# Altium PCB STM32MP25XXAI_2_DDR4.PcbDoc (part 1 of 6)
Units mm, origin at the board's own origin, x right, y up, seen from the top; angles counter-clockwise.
Board outline 172 x 137 mm, 4 copper layers (Top Layer, Signal Layer 1, Signal Layer 2, Bottom Layer), stack 1.614 mm thick; 241 components, 153 nets, 1312 pads, 924 vias.
Unrouted connection lines stored in the file: 13.
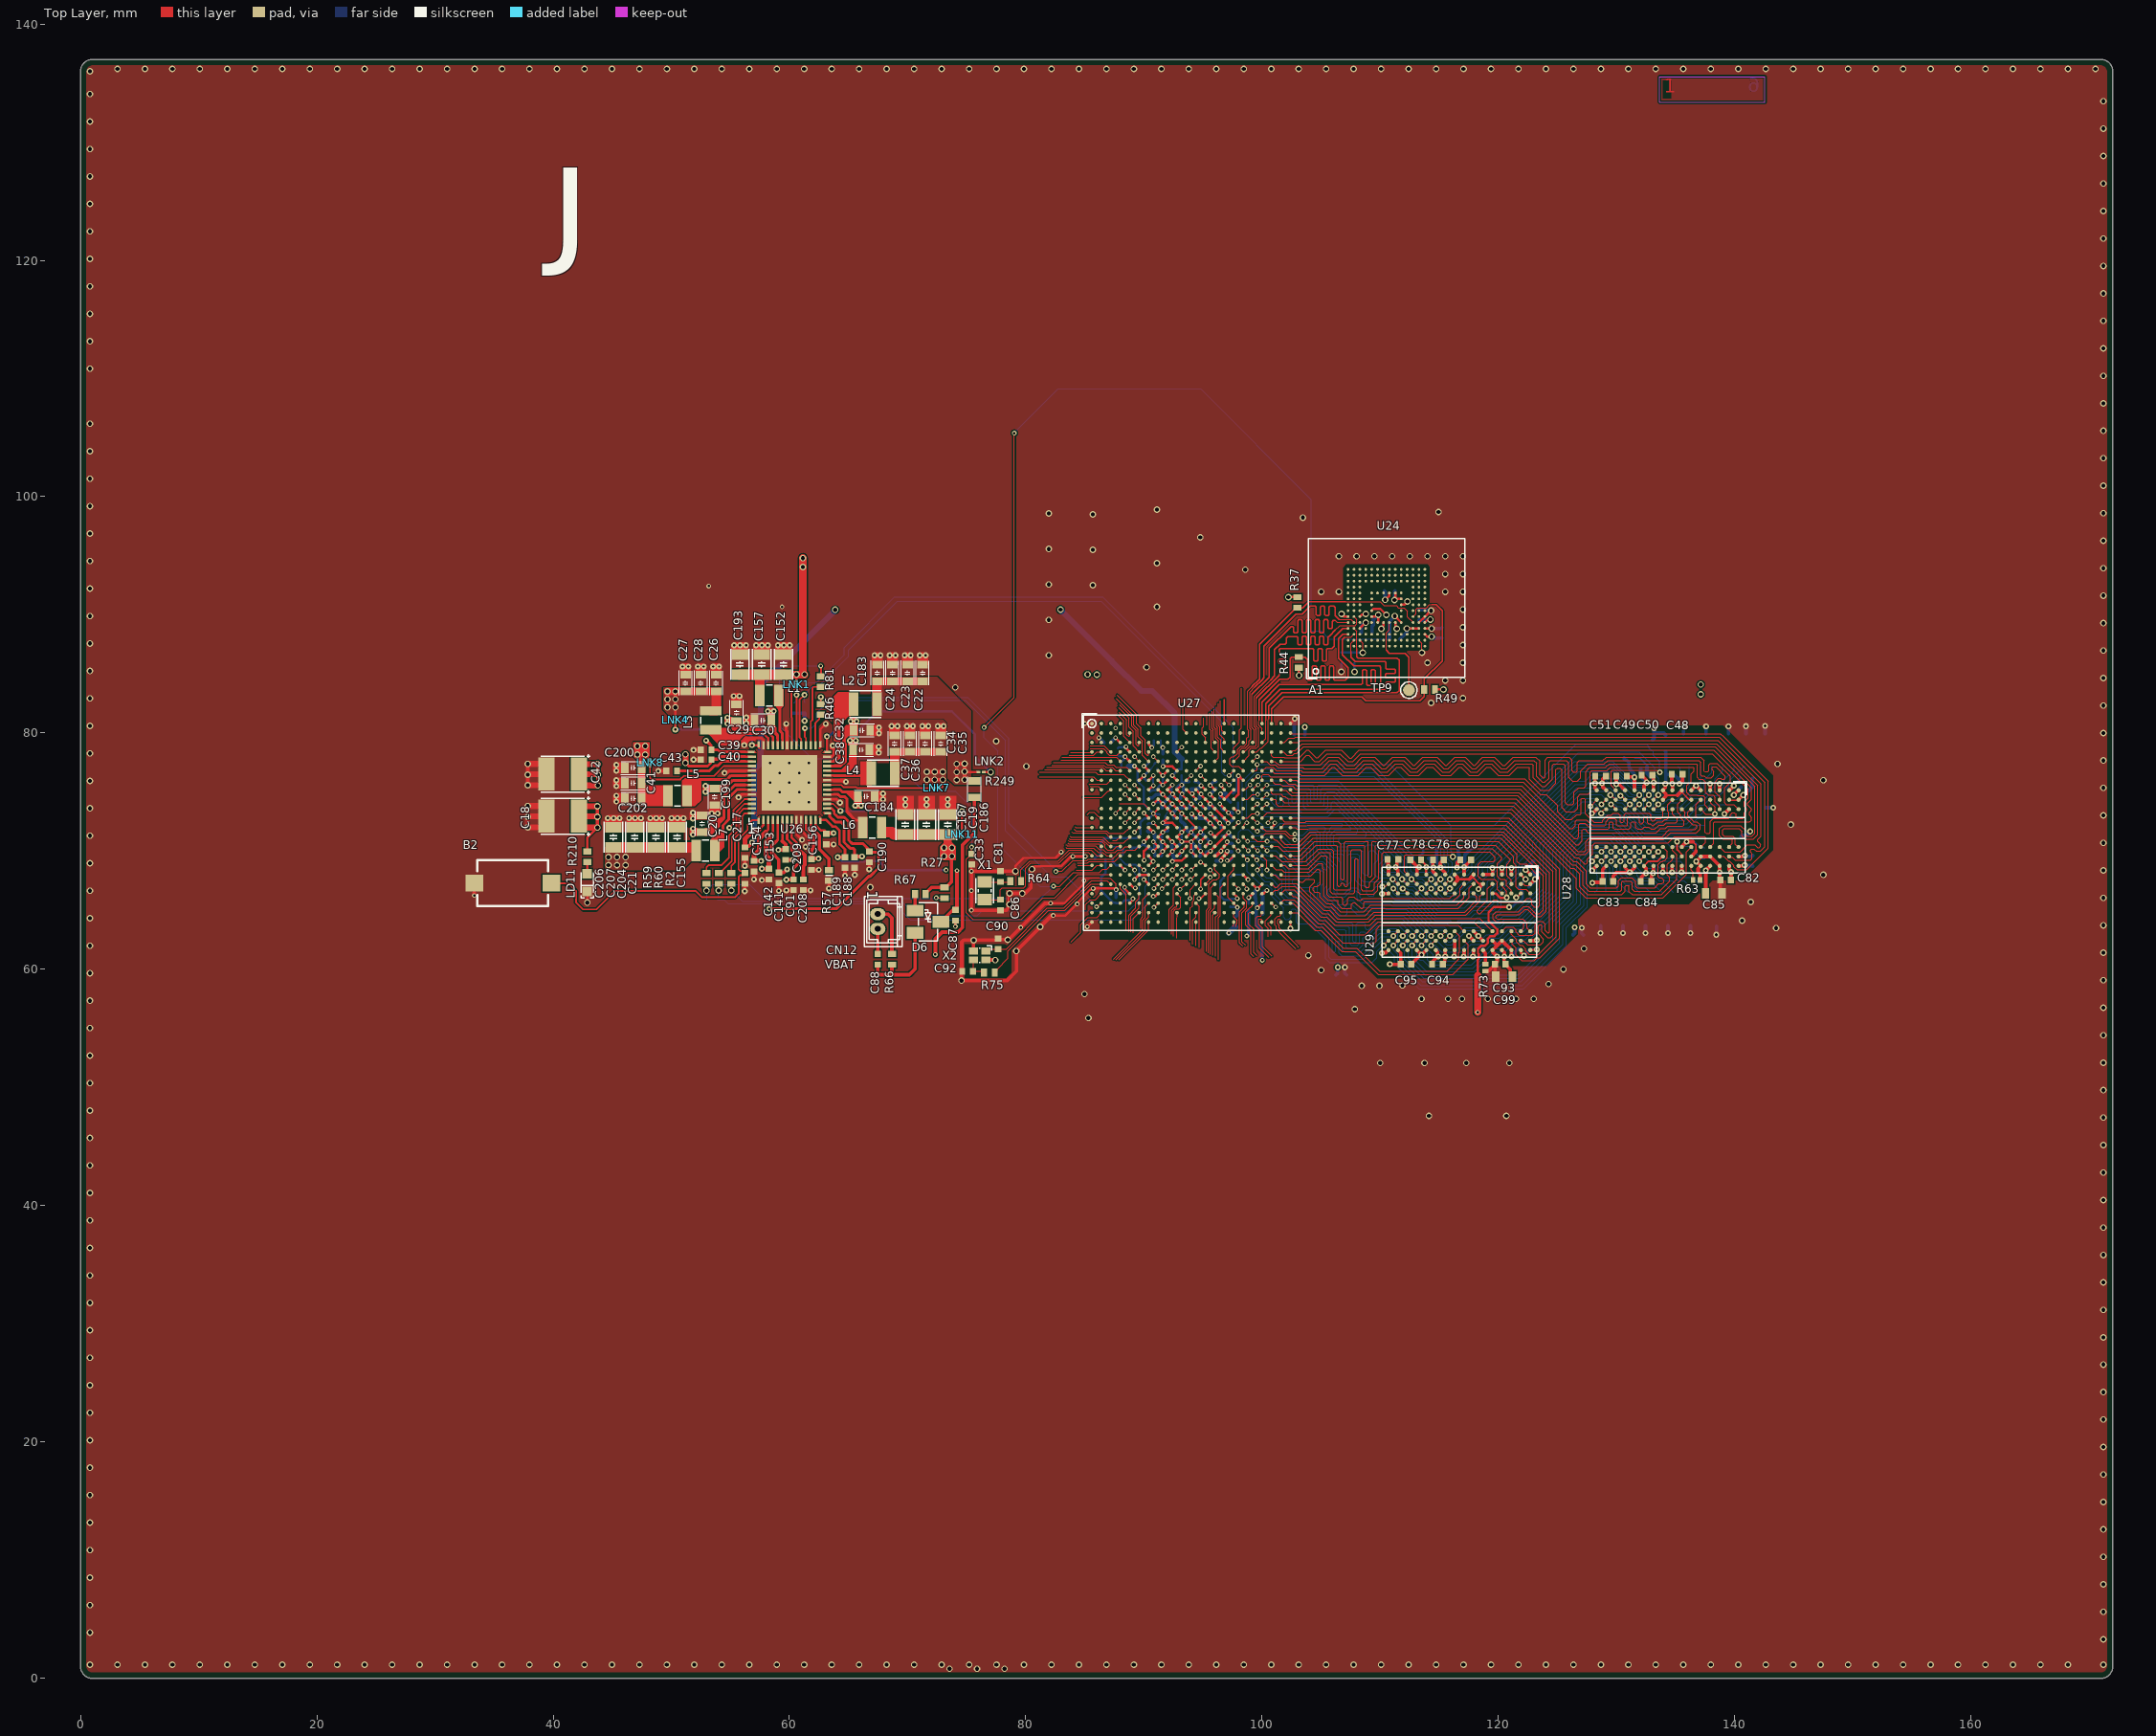
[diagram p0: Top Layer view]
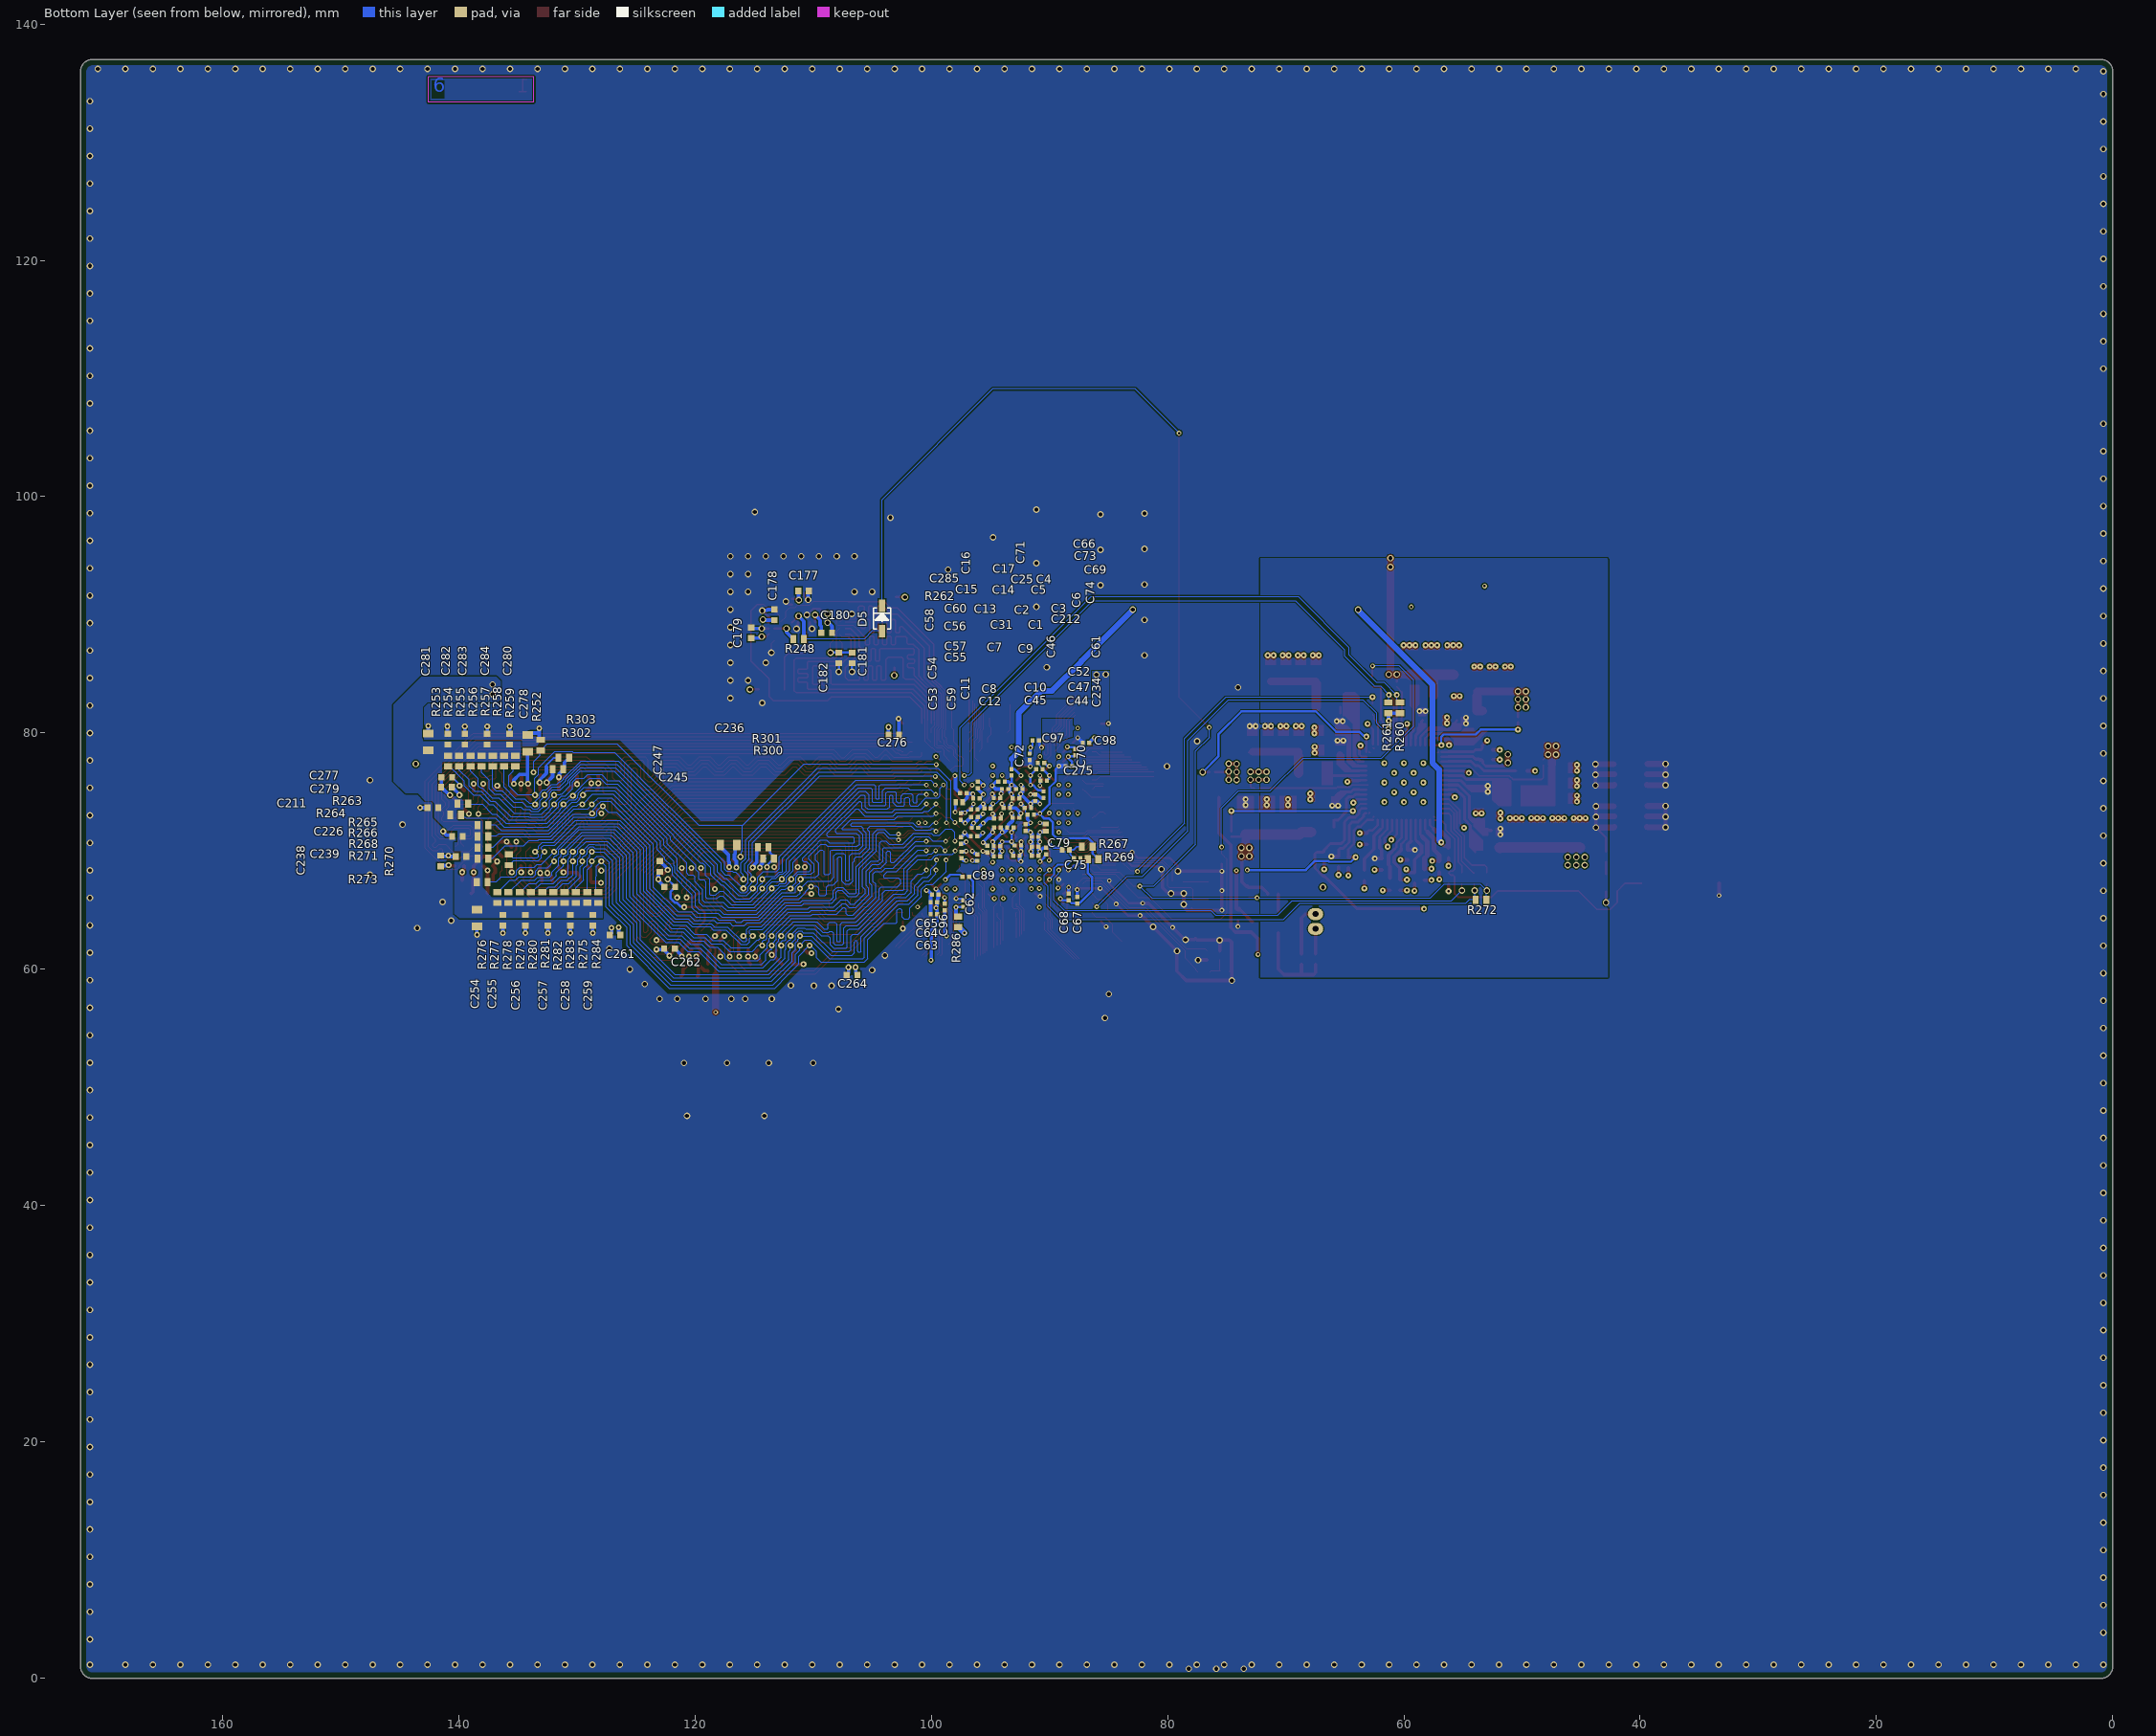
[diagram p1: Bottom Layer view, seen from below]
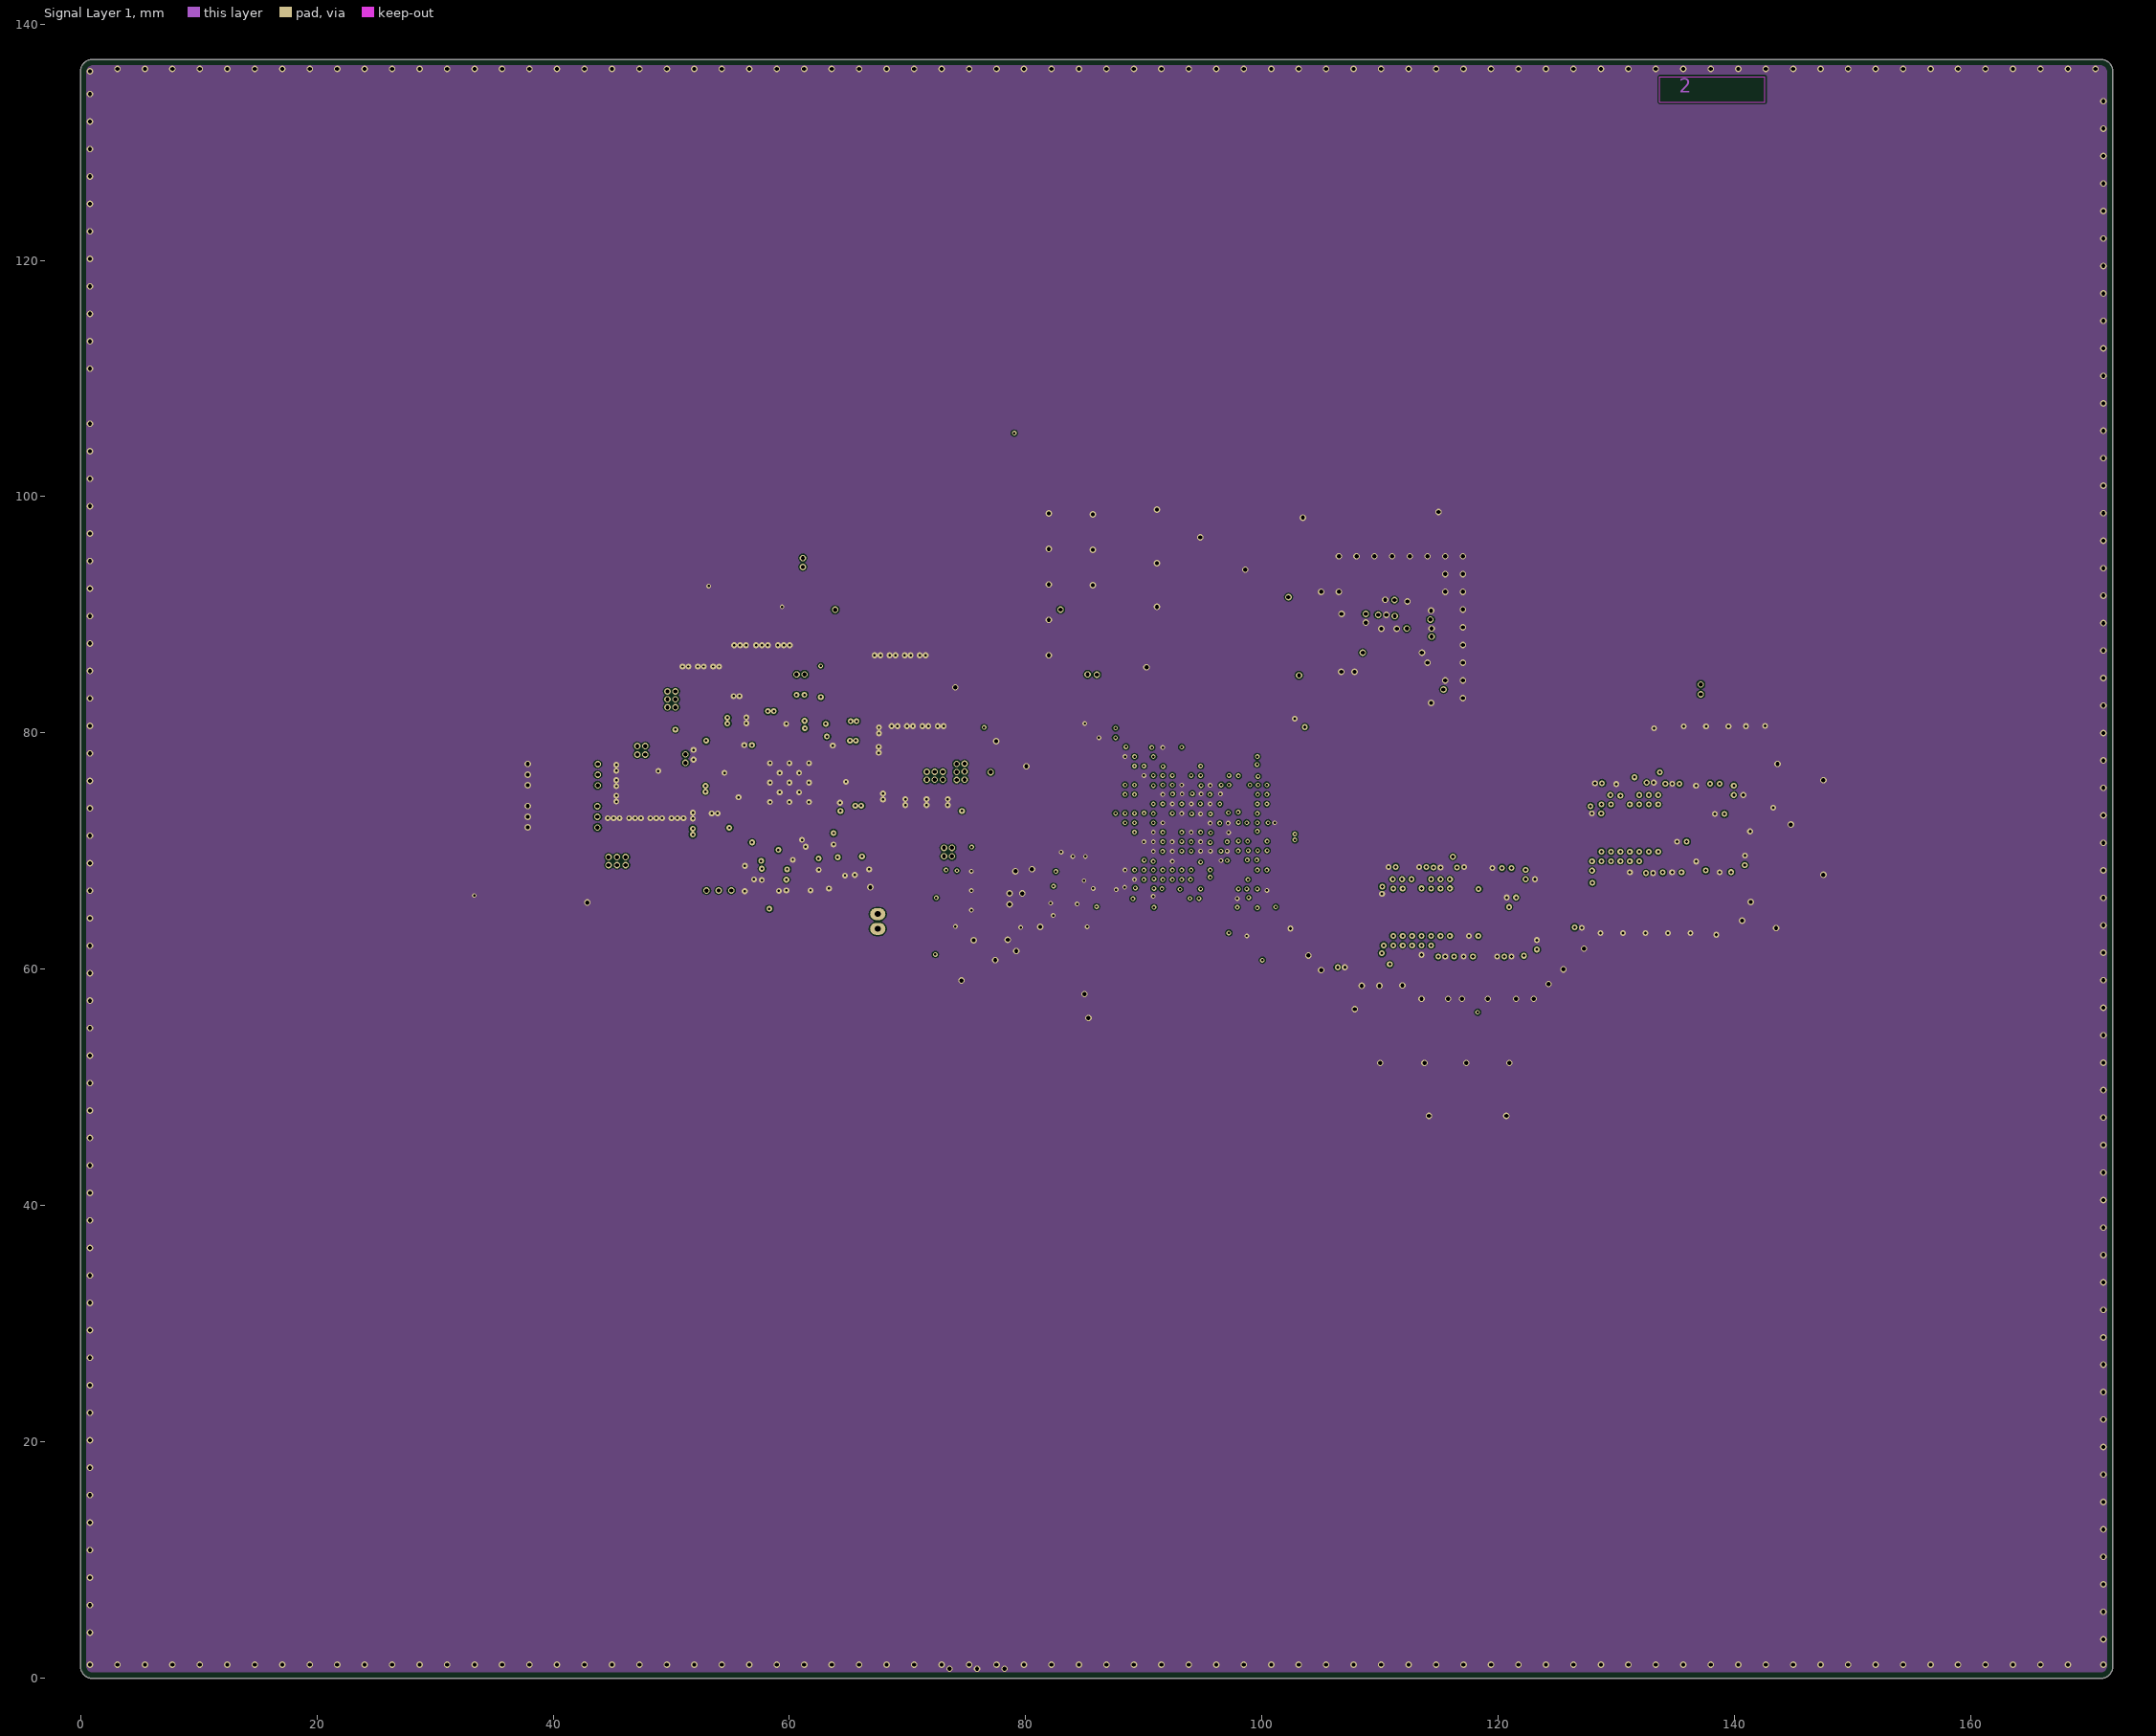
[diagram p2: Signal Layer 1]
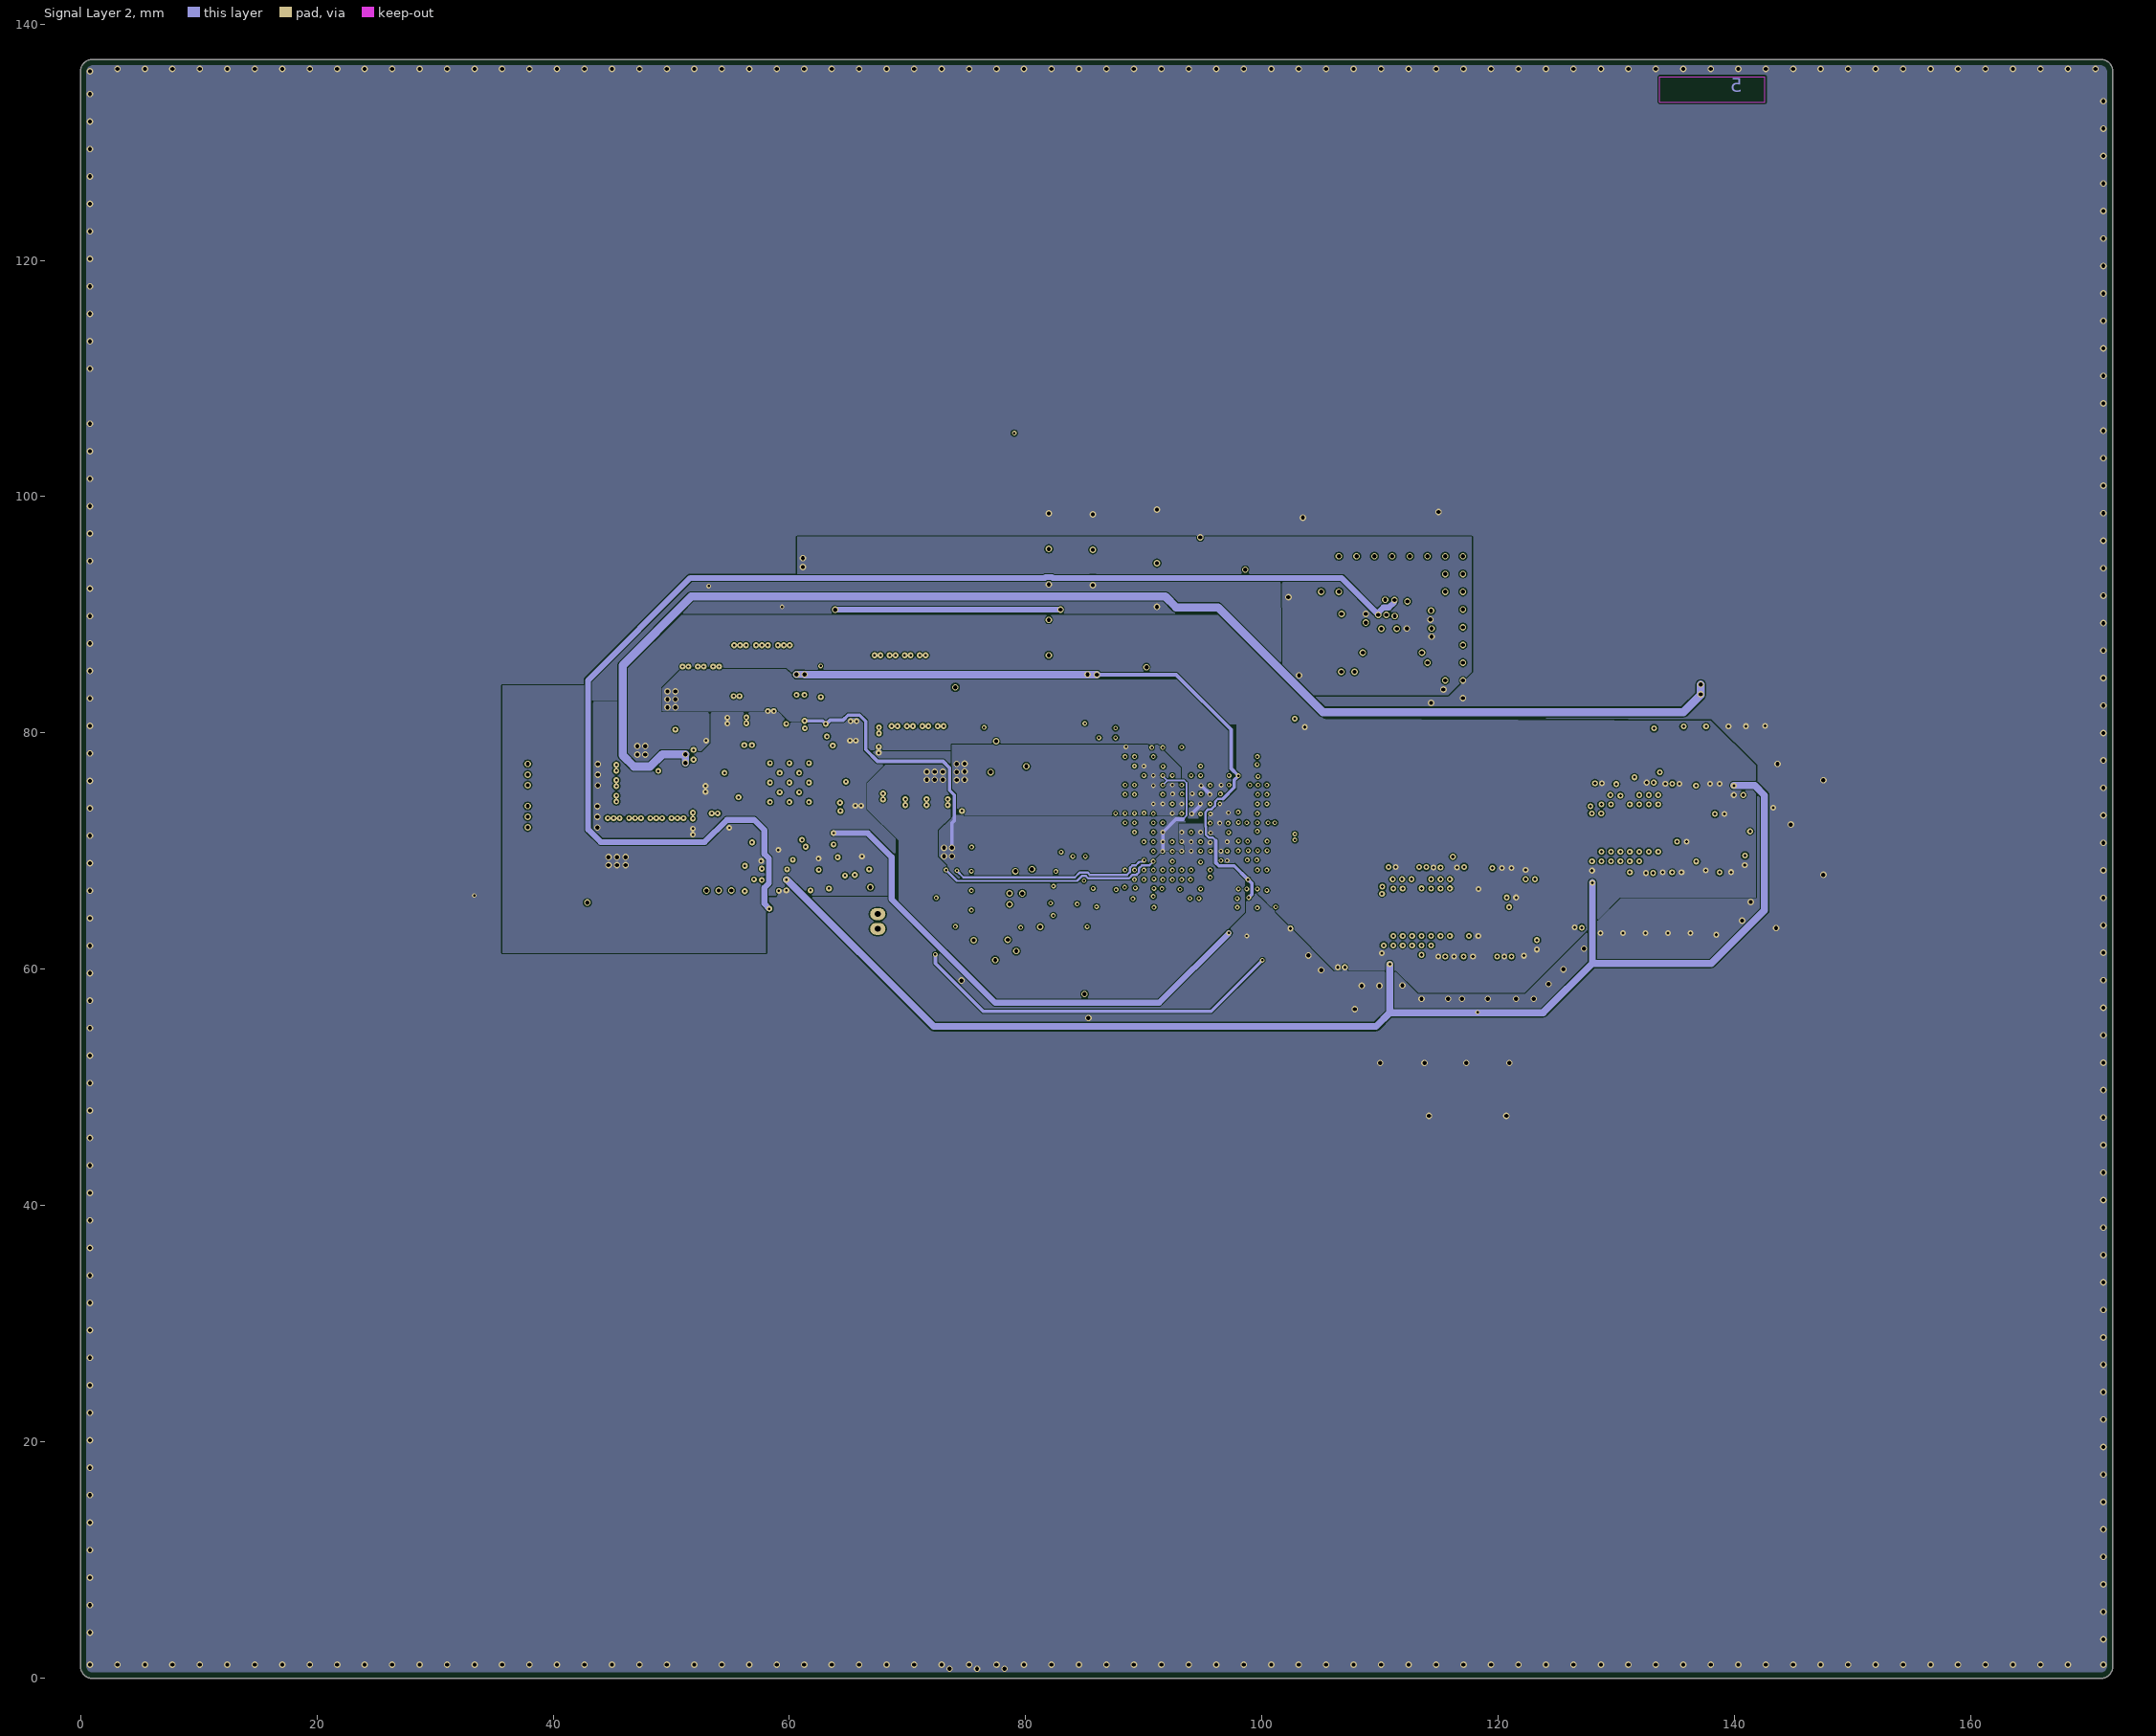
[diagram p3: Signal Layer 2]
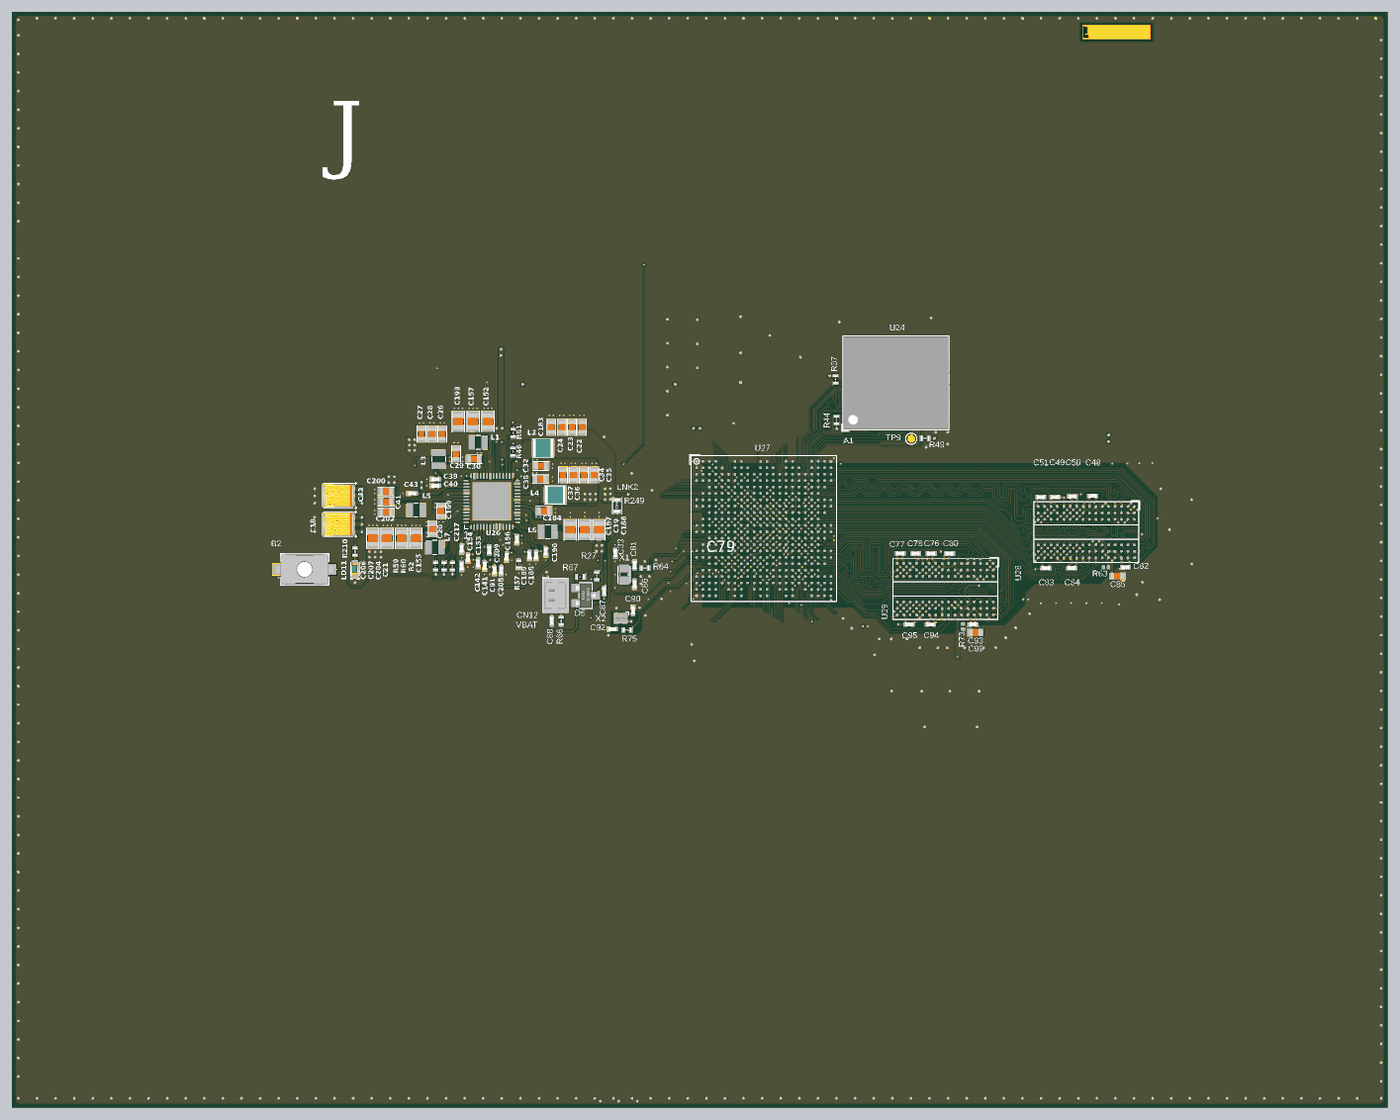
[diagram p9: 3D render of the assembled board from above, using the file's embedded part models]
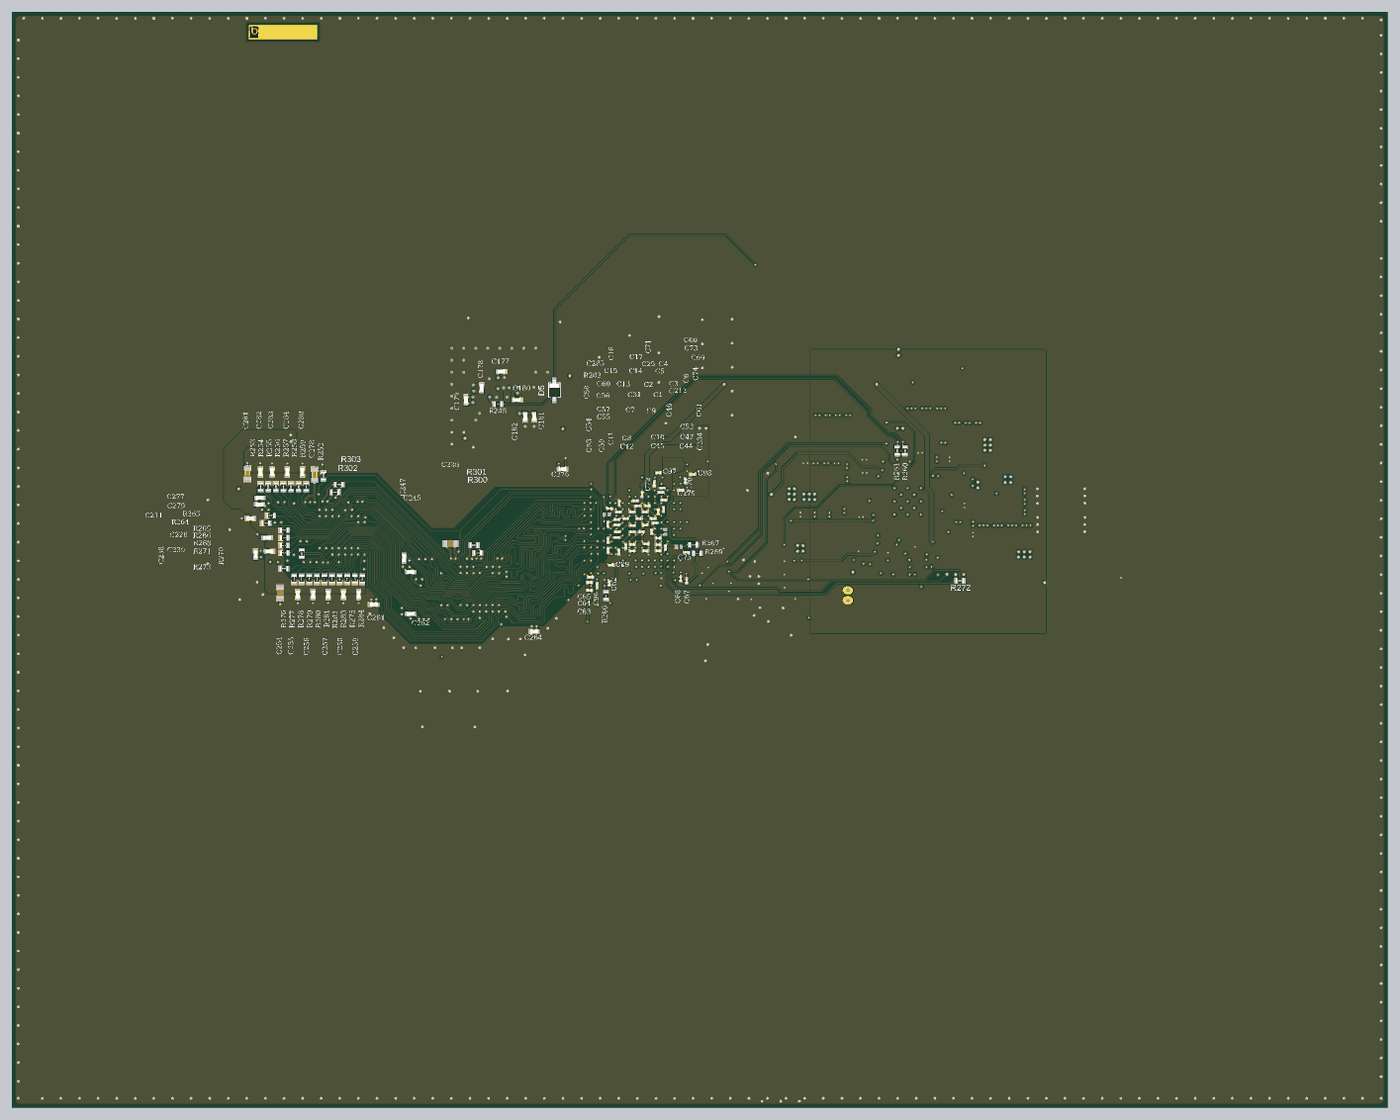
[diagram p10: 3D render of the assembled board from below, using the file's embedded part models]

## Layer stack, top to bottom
Top Solder: solder mask 0.025, Solder Resist, Dk 3.5
Top Layer: signal copper 0.037
Dielectric 1: prepreg 0.07, Dk 3.8
Signal Layer 1: signal copper 0.035
Dielectric 2: core 1.33, Dk 4.3
Signal Layer 2: signal copper 0.035
Dielectric 3: prepreg 0.07, Dk 3.8
Bottom Layer: signal copper 0.037
Bottom Solder: solder mask 0.025, Solder Resist, Dk 3.5

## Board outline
0,1 0,95 0,136 cw(c1,136) 1,137 171,137 cw(c171,136) 172,136 172,1 cw(c171,1) 171,0 1,0 cw(c1,1)

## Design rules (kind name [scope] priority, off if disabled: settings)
BoardOutlineClearance Silkscreen [OnLayer('Top Overlay') or OnLayer('Bottom Overlay')] p1: gap=0 ignorepadtopadclearanceinfootprint=FALSE
BoardOutlineClearance [All] p2: gap=0.5 ignorepadtopadclearanceinfootprint=FALSE
Clearance Clearance_Default [All] p1: gap=0.1 ignorepadtopadclearanceinfootprint=TRUE except(0: Arc-Hole Track-Hole SMDPad-Hole THPad-Hole Via-Hole Fill-Hole Poly-Hole Region-Hole Text-Hole; 0.09: Track-Track Track-SMDPad)
ComponentClearance [All] p1 off: gap=0.2 collisioncheckmode=3 verticalgap=0 showdistances=FALSE
DiffPairsRouting DiffPairsRouting_DDR_100R [InDifferentialPairClass('DPC_DDR_100R')] p1: maxlimit=0.16 minlimit=0.14 mostfreqgap=0.254 toplayer_mingap=0.16 toplayer_prefgap=0.16 toplayer_minwidth=0.09 toplayer_maxwidth=0.09 toplayer_prefwidth=0.09 bottomlayer_mingap=0.16 bottomlayer_prefgap=0.16 bottomlayer_minwidth=0.09 bottomlayer_maxwidth=0.09 bottomlayer_prefwidth=0.09 impedanceprofiledriven=TRUE impedanceprofileid={5106416E-43F8-41F8-8BCA-F68B3FB1C141} impedanceprofilevalue=100.000000 maxuncoupledlength=12.7
FanoutControl Fanout_BGA [IsBGA] p1: bgadir=Out bgaviamode=Closest fanoutstyle=Auto fanoutdirection=Alternating viagrid=0.025 // Fanout_BGA (Default Rule)
FanoutControl Fanout_LCC [IsLCC] p2: bgadir=Out bgaviamode=Closest fanoutstyle=Auto fanoutdirection=Alternating viagrid=0.025 // Fanout_LCC (Default Rule)
FanoutControl Fanout_SOIC [IsSOIC] p3: bgadir=Out bgaviamode=Closest fanoutstyle=Auto fanoutdirection=Alternating viagrid=0.025 // Fanout_SOIC (Default Rule)
FanoutControl Fanout_Small [(CompPinCount < 5)] p4: bgadir=Out bgaviamode=Closest fanoutstyle=Auto fanoutdirection=OutThenIn viagrid=0.025 // Fanout_Small (Default Rule)
FanoutControl Fanout_Default [All] p5: bgadir=Out bgaviamode=Closest fanoutstyle=Auto fanoutdirection=Alternating viagrid=0.025 // Fanout_Default (Default Rule)
HoleSize [All] p1: absolutevalues=TRUE maxlimit=10 minlimit=0.025 maxpercent=80.000 minpercent=20.000
HoleToHoleClearance [All] p1: gap=0.25 allowstackedmicrovias=TRUE
MinimumSolderMaskSliver [All] p1: minsoldermaskwidth=0.07
PlaneConnect [All] p1: planeconnectstyle=Direct reliefexpansion=0.508 reliefentries=4 reliefconductorwidth=0.21 reliefairgap=0.21
PolygonConnect PolygonConnect_Default [All] p1: connectstyle=Direct reliefconductorwidth=0.25 reliefentries=4 polygonreliefangle="90 Angle" airgapwidth=0.25
RoutingVias RoutingVias_Default [All] p1: holewidth=0.15 width=0.4 viastyle="Through Hole" minholewidth=0.15 minwidth=0.4 maxholewidth=0.35 maxwidth=0.6 viatemplateguid#1={BF886351-5902-4D8E-87A9-DD407FAE4AFA} viatemplateguid#2={A479BBDC-94B7-4D18-B59D-B7A18B767B5F} viatemplateguid#3={564DD7E2-F718-4BCE-8A99-5417C9FECCB6} viatemplateguid#4={BB8F4C89-420F-4EBC-9772-FD82009DE81A} viatemplateguid#5={3FF096CA-B7A5-4E0B-A50A-8B2CD18CCC19} viatemplatename#1=v50h25m30mx30 viatemplatename#2=v55h35m40mx40 viatemplatename#3=v40h20m0mx0 viatemplatename#4=v40h20m25mx25 viatemplatename#5=v50h25m0mx0
ShortCircuit ShortCircuit_Link200 [InPadClass('PC_LINK200')] p1: allowed=TRUE
SilkToSilkClearance [All] p1: silktosilkclearance=0.2
SilkToSolderMaskClearance [IsPad] p1: minsilkscreentomaskgap=0.015 clearancetoexposedcopper=TRUE
SolderMaskExpansion [All] p1: expansion=0.1 istentingtop=FALSE
ViasUnderSMD [InPadClass('PC_VIAS-IN-PAD_OK')] p1: allowed=TRUE
Width Width_Default [InNetClass('All Nets')] p1: maxlimit=10 minlimit=0.09 preferedwidth=0.1
16 further rules are at their usual default settings.

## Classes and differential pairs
differential pair DDR_DQS3: +DDR_DQS3_P -DDR_DQS3_N
differential pair DDR_DQS2: +DDR_DQS2_P -DDR_DQS2_N
differential pair DDR_DQS1: +DDR_DQS1_P -DDR_DQS1_N
differential pair DDR_DQS0: +DDR_DQS0_P -DDR_DQS0_N
differential pair DDR_CLK: +DDR_CLK_P -DDR_CLK_N

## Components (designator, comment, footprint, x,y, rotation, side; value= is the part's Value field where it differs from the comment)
B2 "SW_PUSH_SMD_2P" SWI_WE_434121025816 36.59,67.295 r0 top value=434121025816
C1 "Capacitor" C0201_MURATA_GRM033_H0P3 92.825,72.825 r0 bottom value=1uF
C2 "Capacitor" C0201_MURATA_GRM033_H0P3 93.601,73.65 r180 bottom value=1uF
C3 "Capacitor" C0201_MURATA_GRM033_H0P3 91.825,73.65 r180 bottom value=1uF
C4 "Capacitor" C0201_MURATA_GRM033_H0P3 92.55,75.25 r0 bottom value=1uF
C5 "Capacitor" C0201_MURATA_GRM033_H0P3 92.826,74.475 r180 bottom value=1uF
C6 "Capacitor" C0201_MURATA_GRM033_H0P3 91.2,74.525 r270 bottom value=1uF
C7 "Capacitor" C0201_MURATA_GRM033_H0P3 94.4,72 r0 bottom value=1uF
C8 "Capacitor" C0201_MURATA_GRM033_H0P3 94.425,70.425 r180 bottom value=1uF
C9 "Capacitor" C0201_MURATA_GRM033_H0P3 93.3,72 r180 bottom value=1uF
C10 "Capacitor" C0201_MURATA_GRM033_H0P3 92.675,70.48 r0 bottom value=1uF
C11 "Capacitor" C0201_MURATA_GRM033_H0P3 95.25,70.175 r270 bottom value=1uF
C12 "Capacitor" C0201_MURATA_GRM033_H0P3 94.425,69.575 r180 bottom value=1uF
C13 "Capacitor" C0201_MURATA_GRM033_H0P3 95.232,73.625 r0 bottom value=1uF
C14 "Capacitor" C0201_MURATA_GRM033_H0P3 94.425,74.48 r180 bottom value=1uF
C15 "Capacitor" C0201_MURATA_GRM033_H0P3 96.175,74.475 r180 bottom value=1uF
C16 "Capacitor" C0201_MURATA_GRM033_H0P3 96.075,75.6 r90 bottom value=1uF
C17 "Capacitor" C0201_MURATA_GRM033_H0P3 94.05,75.875 r0 bottom value=1uF
C18 "Cap_POL_TANA" CPOL_TCJ-B_1210_H210 40.812,72.961 r180 top value=100uF
C19 "Capacitor" C0805 71.6,72.25 r270 top value=22uF
C20 "Capacitor" C0603 52.6,72.325 r270 top value=10uF
C21 "Capacitor" C0805 50.5,71.173 r270 top value=22uF
C22 "Capacitor" C0603 71.275,85.075 r270 top value=22uF
C23 "Capacitor" C0603 70,85.075 r270 top value=22uF
C24 "Capacitor" C0603 68.725,85.075 r270 top value=22uF
C25 "Capacitor" C0201_MURATA_GRM033_H0P3 93.75,75.25 r0 bottom value=1uF
C26 "Capacitor" C0603 53.8,84.225 r270 top value=22uF
C27 "Capacitor" C0603 51.2,84.225 r270 top value=22uF
C28 "Capacitor" C0603 52.5,84.225 r270 top value=22uF
C29 "Capacitor" C0603 55.525,81.725 r270 top value=10uF
C30 "Capacitor" C0603 57.75,81.075 r0 top value=10uF
C31 "Capacitor" C0201_MURATA_GRM033_H0P3 94.4,72.775 r180 bottom value=1uF
C32 "Capacitor" C0603 66.125,80.225 r180 top value=10uF
C33 "Capacitor" C0402 75.425,69.325 r90 top value=10nF
C34 "Capacitor" C0603 71.5,79.1 r270 top value=22uF
C35 "Capacitor" C0603 72.8,79.1 r270 top value=22uF
C36 "Capacitor" C0603 70.2,79.1 r270 top value=22uF
C37 "Capacitor" C0603 68.9,79.1 r270 top value=22uF
C38 "Capacitor" C0603 66.075,78.575 r180 top value=10uF
C39 "Capacitor" C0402 52.945,78.575 r0 top value=10uF
C40 "Capacitor" C0402 52.945,77.75 r0 top value=10uF
C41 "Capacitor" C0603 46.775,75.75 r0 top value=22uF
C42 "Cap_POL_TANA" CPOL_TCJ-B_1210_H210 40.812,76.523 r180 top value=100uF
C43 "Capacitor" C0402 50.035,76.8 r0 top value=1uF
C44 "Capacitor" C0201_MURATA_GRM033_H0P3 91.2,69.6 r180 bottom value=1uF
C45 "Capacitor" C0201_MURATA_GRM033_H0P3 92.8,69.6 r0 bottom value=1uF
C46 "Capacitor" C0201_MURATA_GRM033_H0P3 92.025,72 r270 bottom value=1uF
C47 "Capacitor" C0201_MURATA_GRM033_H0P3 91.2,70.388 r180 bottom value=1uF
C48 "Capacitor" C0402 135.125,76.5 r0 top value=100nF
C49 "Capacitor" C0402 130.425,76.35 r0 top value=100nF
C50 "Capacitor" C0402 132.575,76.425 r180 top value=100nF
C51 "Capacitor" C0402 128.65,76.35 r0 top value=100nF
C52 "Capacitor" C0201_MURATA_GRM033_H0P3 91.2,71.2 r0 bottom value=1uF
C53 "Capacitor" C0201_MURATA_GRM033_H0P3 97.45,69.675 r270 bottom value=1uF
C54 "Capacitor" C0201_MURATA_GRM033_H0P3 97.475,70.9 r90 bottom value=1uF
C55 "Capacitor" C0201_MURATA_GRM033_H0P3 96.375,71.275 r180 bottom value=1uF
C56 "Capacitor" C0201_MURATA_GRM033_H0P3 96.349,72.875 r180 bottom value=1uF
C57 "Capacitor" C0201_MURATA_GRM033_H0P3 96.301,71.974 r0 bottom value=1uF
C58 "Capacitor" C0201_MURATA_GRM033_H0P3 97.5,72.925 r90 bottom value=1uF
C59 "Capacitor" C0201_MURATA_GRM033_H0P3 96.1,69.45 r90 bottom value=1uF
C60 "Capacitor" C0201_MURATA_GRM033_H0P3 96.356,73.524 r0 bottom value=1uF
C61 "Capacitor" C0201_H0P5 90.317,71.988 r90 bottom value=4.7uF
C62 "Capacitor" C0201_MURATA_GRM033_H0P3 97.3,65.575 r270 bottom value=100nF
C63 "Capacitor" C0201_MURATA_GRM033_H0P3 99.775,64.675 r180 bottom value=100nF
C64 "Capacitor" C0201_MURATA_GRM033_H0P3 99.775,65.675 r180 bottom value=100nF
C65 "Capacitor" C0201_MURATA_GRM033_H0P3 99.65,66.325 r180 bottom value=100nF
C66 "Capacitor" C0201_MURATA_GRM033_H0P3 90.7,77.475 r180 bottom value=100nF
C67 "Capacitor" C0201_MURATA_GRM033_H0P3 87.63,65.845 r270 bottom value=1uF
C68 "Capacitor" C0201_MURATA_GRM033_H0P3 88.375,66.125 r270 bottom value=100nF
C69 "Capacitor" C0201_MURATA_GRM033_H0P3 90.48,75.97 r0 bottom value=100nF
C70 "Capacitor" C0201_MURATA_GRM033_H0P3 87.8,78.375 r90 bottom value=100nF
C71 "Capacitor" C0201_MURATA_GRM033_H0P3 93.201,76.675 r90 bottom value=100nF
C72 "Capacitor" C0201_MURATA_GRM033_H0P3 91.675,77.975 r270 bottom value=100nF
C73 "Capacitor" C0201_MURATA_GRM033_H0P3 90.85,76.925 r0 bottom value=100nF
C74 "Capacitor" C0201_MURATA_GRM033_H0P3 90.5,74.775 r90 bottom value=100nF
C75 "Capacitor" C0201_MURATA_GRM033_H0P3 87.65,69.425 r0 bottom value=100nF
C76 "Capacitor" C0402 114.925,69.275 r180 top value=100nF
C77 "Capacitor" C0402 111.075,69.3 r0 top value=100nF
C78 "Capacitor" C0402 113,69.275 r0 top value=100nF
C79 "Capacitor" C0201_H0P5 88.6,70.125 r180 bottom value=2.2uF
C80 "Capacitor" C0402 117.225,69.275 r180 top value=100nF
C81 "Capacitor" C0402 77.85,67.85 r90 top value=6.8pF
C82 "Capacitor" C0402 139.225,67.55 r0 top value=100nF
C83 "Capacitor" C0402 129.275,67.45 r180 top value=100nF
C84 "Capacitor" C0402 132.5,67.45 r180 top value=100nF
C85 "Capacitor" C0603 138.225,66.425 r180 top value=10uF
C86 "Capacitor" C0402 77.85,65.45 r270 top value=6.8pF
C87 "" C0402 74.05,64.575 r90 top value=100nF
C88 "Capacitor" C0402 67.475,60.85 r270 top value=2.2uF
C89 "Capacitor" C0201_MURATA_GRM033_H0P3 97.075,67.825 r0 bottom value=100nF
C90 "Capacitor" C0402 77.65,62.15 r270 top value=6.8pF
C91 "Capacitor" C0402 60.345,67.16 r270 top value=4.7uF
C92 "Capacitor" C0402 75.075,59.825 r180 top value=6.8pF
C93 "Capacitor" C0402 120.15,60.425 r0 top value=100nF
C94 "Capacitor" C0402 114.844,60.422 r180 top value=100nF
C95 "Capacitor" C0402 112.175,60.425 r180 top value=100nF
C96 "Capacitor" C0201_MURATA_GRM033_H0P3 98.85,65.275 r90 bottom value=100nF
C97 "Capacitor" C0201_MURATA_GRM033_H0P3 91.15,79.375 r180 bottom value=100nF
C98 "Capacitor" C0201_MURATA_GRM033_H0P3 86.9,79.175 r0 bottom value=100nF
C99 "Capacitor" C0603 120.475,59.4 r0 top value=10uF
C141 "Capacitor" C0402 59.1,67.75 r270 top value=4.7uF
C142 "Capacitor" C0402 58.275,68.06 r270 top value=4.7uF
C152 "Capacitor" C0805 59.5,85.8 r270 top value=22uF
C153 "Capacitor" C0402 59.675,69.72 r90 top value=1uF
C154 "Capacitor" C0402 57,68.725 r90 top value=1uF
C155 "Capacitor" C0402 56.227,67.695 r90 top value=10nF
C156 "Capacitor" C0402 63.125,71.02 r90 top value=4.7uF
C157 "Capacitor" C0805 57.65,85.8 r270 top value=22uF
C177 "Capacitor" C0402 110.8,92.025 r0 bottom value=100nF
C178 "Capacitor" C0402 113.275,90 r270 bottom value=2.2uF
C179 "Capacitor" C0402 115.225,88.475 r270 bottom value=100nF
C180 "Capacitor" C0402 108.85,88.475 r0 bottom value=2.2uF
C181 "Capacitor" C0402 106.7,86.35 r90 bottom value=2.2uF
C182 "Capacitor" C0402 107.825,86.35 r90 bottom value=100nF
C183 "Capacitor" C0603 67.45,85.075 r270 top value=22uF
C184 "Capacitor" C0603 66.497,74.625 r180 top value=10uF
C186 "Capacitor" C0805 73.4,72.25 r270 top value=22uF
C187 "Capacitor" C0805 69.8,72.25 r270 top value=22uF
C188 "Capacitor" C0402 65.525,69.04 r90 top value=1uF
C189 "Capacitor" C0402 64.7,69.04 r90 top value=4.7uF
C190 "Capacitor" C0402 66.75,69.515 r270 top value=4.7uF
C193 "Capacitor" C0805 55.8,85.8 r270 top value=22uF
C199 "Capacitor" C0603 53.675,74.6 r90 top value=10uF
C200 "Capacitor" C0603 46.775,77.05 r0 top value=22uF
C202 "Capacitor" C0603 46.775,74.45 r0 top value=22uF
C204 "Capacitor" C0805 48.7,71.173 r270 top value=22uF
C206 "Capacitor" C0805 45.1,71.173 r270 top value=22uF
C207 "Capacitor" C0805 46.9,71.173 r270 top value=22uF
C208 "Capacitor" C0402 61.17,67.16 r270 top value=4.7uF
C209 "Capacitor" C0402 61.85,68.87 r90 top value=4.7uF
C211 "Capacitor" C0402 142.175,73.675 r180 bottom value=100nF
C212 "Capacitor" C0201_MURATA_GRM033_H0P3 91.585,73.1 r180 bottom value=100nF
C217 "Capacitor" C0402 56.225,69.87 r270 top value=4.7uF
C226 "Capacitor" C0402 140.1,71.25 r180 bottom value=100nF
C234 "Capacitor" C0201_MURATA_GRM033_H0P3 90.275,70.01 r270 bottom value=100nF
C236 "Capacitor" C0603 117.15,70.525 r180 bottom value=10uF
C238 "Capacitor" C0402 141.525,69.175 r270 bottom value=100nF
C239 "Capacitor" C0402 139.8,69.55 r180 bottom value=100nF
C245 "Capacitor" C0402 122.125,66.975 r180 bottom value=100nF
C247 "Capacitor" C0402 122.975,68.7 r90 bottom value=100nF
C254 "Capacitor" C0603 138.45,64.35 r90 bottom value=10uF
C255 "Capacitor" C0402 136.25,64.15 r90 bottom value=100nF
C256 "Capacitor" C0402 134.35,64.15 r90 bottom value=100nF
C257 "Capacitor" C0402 132.45,64.15 r90 bottom value=100nF
C258 "Capacitor" C0402 130.55,64.15 r90 bottom value=100nF
C259 "Capacitor" C0402 128.65,64.15 r90 bottom value=100nF
C261 "Capacitor" C0402 126.75,62.9 r180 bottom value=100nF
C262 "Capacitor" C0402 122.15,61.75 r0 bottom value=100nF
C264 "Capacitor" C0402 106.7,59.525 r180 bottom value=100nF
C275 "Capacitor" C0201_MURATA_GRM033_H0P3 88.35,77.2 r0 bottom value=100nF
C276 "Capacitor" C0402 103.17,79.846 r0 bottom value=100nF
C277 "Capacitor" C0402 141,76.25 r180 bottom value=100nF
C278 "Capacitor" C0603 134.15,79.125 r270 bottom value=10uF
C279 "Capacitor" C0402 141.025,75.425 r180 bottom value=100nF
C280 "Capacitor" C0402 135.675,79.475 r270 bottom value=100nF
C281 "Capacitor" C0603 142.575,79.25 r270 bottom value=10uF
C282 "Capacitor" C0402 140.925,79.475 r270 bottom value=100nF
C283 "Capacitor" C0402 139.475,79.475 r270 bottom value=100nF
C284 "Capacitor" C0402 137.575,79.475 r270 bottom value=100nF
C285 "Capacitor" C0201_MURATA_GRM033_H0P3 97.28,74.91 r0 bottom value=100nF
CN12 "" CON_MOLEX_53047-0210 67.475,64.05 r270 top value="Header 2x1"
D5 "BAT60JFILM" DIO_SOD323 104.175,89.7 r90 bottom
D6 "DIODE_3P_DUAL_COMMON_CATHODE" DIO_SOT23 71.725,64.025 r270 top value=BAT54CFILM
L1 "Inductor" IND_2016_MURATA_LQM2MPN2R2NG0 58.295,83.175 r180 top value=2.2uH
L2 "Inductor" IND_2520_TOKO_DFE252012P 66.415,82.45 r0 top value=0.68µH
L3 "Inductor" IND_2016_MURATA_LQM2MPN2R2NG0 53.35,81.075 r90 top value=0.68uH
L4 "Inductor" IND_2520_TOKO_DFE252012P 67.925,76.6 r0 top value=0.68µH
L5 "Inductor" IND_2016_MURATA_LQM2MPN2R2NG0 50.525,74.7 r180 top value=0.68uH
L6 "Inductor" IND_2016_MURATA_LQM2MPN2R2NG0 67,72 r0 top value=2.2uH
L7 "Inductor" IND_2016_MURATA_LQM2MPN2R2NG0 52.9,70.05 r180 top value=0.68uH
LD11 "LED_green" LED_0603_OSRAM_LG-Q396-PS-35_GREEN_1A2K_H0P4 42.887,67.327 r270 top value=GREEN
LNK1 "link_200" LINK200 60.6,84.123 r0 top
LNK2 "link_200" LINK200 76.219,76.687 r90 top
LNK4 "link_200" LINK200 50.35,81.125 r180 top
LNK7 "link_200" LINK200 72.45,75.35 r270 top
LNK8 "link_200" LINK200 48.2,77.498 r0 top
LNK11 "link_200" LINK200 74.6,71.44 r180 top
R2 "" R0402 55.08,67.695 r90 top value=0R
R27 "Resistor" R0402 73.125,66.475 r90 top value=10K
R37 "Resistor" R0402 102.975,91.05 r90 top value=10K
R44 "Resistor" R0402 103.1,85.978 r270 top value=10K
R46 "" R0402 62.65,81.998 r270 top value=0R
R49 "Resistor" R0402 114.175,83.685 r0 top value=10K
R57 "" R0402 63.35,67.95 r90 top value=0R
R59 "" R0402 52.98,67.695 r90 top value=0R
R60 "" R0402 54.03,67.695 r90 top value=0R
R63 "Resistor" R0201_H0P23 136.775,67.55 r180 top value=240R
R64 "" R0402 79.15,67.45 r180 top value=0R
R66 "Resistor" R0402 68.675,60.845 r270 top value=20R
R67 "Resistor" R0402 71.075,66.375 r0 top value=0R
R73 "Resistor" R0201_H0P23 118.9,60.15 r90 top value=240R
R75 "" R0402 76.925,59.725 r0 top value=0R
R81 "" R0402 62.663,84.348 r270 top value=0R
R210 "Resistor" R0402 42.887,69.52 r270 top value=270R
R248 "Resistor" R0402 111.225,87.95 r0 bottom value=10K
R249 "Resistor" R0603 75.65,75.25 r270 top value=0R
R252 "Resistor" R0402 133.05,78.975 r270 bottom value=10K
R253 "Resistor" R0402 140.9,77.625 r90 bottom value=56R
R254 "Resistor" R0402 139.95,77.625 r90 bottom value=56R
R255 "Resistor" R0402 139,77.625 r90 bottom value=56R
R256 "Resistor" R0402 138.05,77.625 r90 bottom value=56R
R257 "Resistor" R0402 137.1,77.625 r90 bottom value=56R
R258 "Resistor" R0402 136.15,77.625 r90 bottom value=56R
R259 "Resistor" R0402 135.2,77.625 r90 bottom value=56R
R260 "Resistor" R0402 60.33,82.13 r270 bottom value=1K5
R261 "Resistor" R0402 61.305,82.13 r270 bottom value=1K5
R262 "Resistor" R0201_H0P23 97.624,74.149 r0 bottom value=240R
R263 "Resistor" R0402 139.65,74.025 r0 bottom value=56R
R264 "Resistor" R0402 140.25,73.075 r0 bottom value=56R
R265 "Resistor" R0402 137.95,72.2 r0 bottom value=56R
R266 "Resistor" R0402 137.95,71.25 r0 bottom value=56R
R267 "" R0402 86.8,70.375 r180 bottom value=0R
R268 "Resistor" R0402 137.95,70.3 r0 bottom value=56R
R269 "" R0402 86.304,69.315 r0 bottom value=0R
R270 "Resistor" R0402 135.75,69.275 r90 bottom value=100R
R271 "Resistor" R0402 137.95,69.35 r0 bottom value=56R
R272 "Resistor" R0402 53.475,65.879 r0 bottom value=10K
R273 "Resistor" R0402 138,67.375 r0 bottom value=56R
R275 "Resistor" R0402 129.12,66.08 r270 bottom value=56R
R276 "Resistor" R0402 136.725,66.075 r270 bottom value=56R
R277 "Resistor" R0402 135.775,66.075 r270 bottom value=56R
R278 "Resistor" R0402 134.825,66.075 r270 bottom value=56R
R279 "Resistor" R0402 133.875,66.075 r270 bottom value=56R
R280 "Resistor" R0402 132.925,66.075 r270 bottom value=56R
R281 "Resistor" R0402 131.975,66.075 r270 bottom value=56R
R282 "Resistor" R0402 131.025,66.075 r270 bottom value=56R
R283 "Resistor" R0402 130.075,66.075 r270 bottom value=56R
R284 "Resistor" R0402 128.175,66.075 r270 bottom value=56R
R286 "" R0402 97.725,64.025 r90 bottom value=0R
R300 "Resistor" R0402 113.775,69.375 r0 bottom value=1K
R301 "Resistor" R0402 114.225,70.325 r180 bottom value=1K
R302 "Resistor" R0402 131.6,76.95 r0 bottom value=1K
R303 "Resistor" R0402 131.1,77.9 r180 bottom value=1K
TP9 "Test Point" TP_SMD_1MM 112.43,83.629 r90 top value=N/A
U24 "eMMC_THGBMTG5D1LBAIL" ICC_P-WFBGA153_13X11P5_P050 110.525,90.6 r0 top locked value=THGBMTG5D1LBAIL
U26 "STPMIC25APQR" ICC_QFN56-EPAD_6P5X6P5_P040 60,75.8 r90 top
U27 "STM32MP257FAI3" ICC_LFBGA436_18X18_P080_H1P70_STM32MP257_CODE-B0D1 94,72.4 r0 top locked
U28 "MT40A1G16TB-062E IT:F" ICC_FBGA96_TB_7P5X13_P080 134.325,71.95 r270 top locked
U29 "MT40A1G16TB-062E IT:F" ICC_FBGA96_TB_7P5X13_P080 116.7,64.825 r270 top locked
X1 "XTAL_2_PINS" CRY_NX2012SA_2P 76.525,66.65 r270 top value=32.768KHz
X2 "XTAL_4_PINS" CRY_NX1612SA_4P 76.098,61.176 r180 top value=40MHz

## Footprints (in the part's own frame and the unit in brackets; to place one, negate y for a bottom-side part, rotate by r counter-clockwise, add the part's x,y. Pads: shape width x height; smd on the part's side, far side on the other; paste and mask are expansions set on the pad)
C0201_H0P5 [mm] "MCD-01534"
  rect 0.4x0.5 smd mask+0.05: 1(-0.3,0) 2(0.3,0)
  body extent -0.35,-0.2 0.35,0.2, height 0.55
C0201_MURATA_GRM033_H0P3 [mm] "GRM033R60J105ME11"
  rect 0.35x0.35 smd mask+0.05: 1(-0.275,0) 2(0.275,0)
  body extent -0.32,-0.17 0.32,0.17, height 0.33
C0402 [mm]
  rect 0.51x0.56 smd mask+0.05: 1(-0.45,0) 2(0.45,0)
  body extent -0.5,-0.3 0.5,0.3, height 0.4
C0603 [mm]
  rect 0.64x0.89 smd mask+0.05: 1(-0.7,0) 2(0.7,0)
  silkscreen extent -1.05,-0.55 1.02,0.55, body extent -0.9,-0.5 0.9,0.5, height 1.4
C0805 [mm]
  rect 0.9x1.4 smd mask+0.05: 1(-0.85,0) 2(0.85,0)
  silkscreen extent -1.3,-0.77 1.3,0.77, body extent -1.1,-0.7 1.1,0.7, height 1.35
CON_MOLEX_53047-0210 [mm]
  oval 1x1.3 hole 0.5 mask+0.05: 1(-0.625,0) 2(0.625,0)
  silkscreen extent -2.12,-1.15 2.13,2.05, body extent -2.13,-1.15 2.13,2.05, height 4.2
CPOL_TCJ-B_1210_H210 [mm] "MCD-01791"
  rect 1.35x2.8 smd mask+0.05: 1(-1.375,0) 2(1.375,0)
  silkscreen extent -2.33,-1.68 1.85,1.68, body extent -1.85,-1.5 1.85,1.5, height 2.11
CRY_NX1612SA_4P [mm] "MCD-02262"
  rect 0.75x0.6 smd mask+0.038: 1(-0.525,-0.375) 2(0.525,-0.375) 3(0.525,0.375) 4(-0.525,0.375)
  silkscreen extent -1.02,-0.8 0.03,0.6, body extent -0.8,-0.6 0.8,0.6, height 0.51
CRY_NX2012SA_2P [mm]
  rect 1x1.25 smd mask+0.05: 1(-0.75,0) 2(0.75,0)
  silkscreen extent -1.05,-0.75 1.05,0.75, body extent -1.05,-0.63 1.05,0.63, height 0.6
DIO_SOD323 [mm]
  rect 1.06x0.54 smd mask+0.05: 1(-1.07,0) 2(1.07,0)
  silkscreen extent -0.9,-0.72 0.9,0.72, body extent -1.3,-0.78 1.3,0.78, height 1.17
DIO_SOT23 [mm]
  rect 1x1.4 smd mask+0.05: 1(-0.95,-1.1) 2(0.95,-1.1) 3(0,1.1)
  silkscreen extent -1.63,-0.82 1.63,0.82, body extent -1.56,-1.25 1.56,1.25, height 1.1
ICC_FBGA96_TB_7P5X13_P080 [mm] "MCD-03523"
  round 0.35 smd mask+0.05: A1(-3.2,6) A2(-2.4,6) A3(-1.6,6) A7(1.6,6) A8(2.4,6) A9(3.2,6) B1(-3.2,5.2) B2(-2.4,5.2) B3(-1.6,5.2) B7(1.6,5.2) B8(2.4,5.2) B9(3.2,5.2) C1(-3.2,4.4) C2(-2.4,4.4) C3(-1.6,4.4) C7(1.6,4.4) C8(2.4,4.4) C9(3.2,4.4) D1(-3.2,3.6) D2(-2.4,3.6) D3(-1.6,3.6) D7(1.6,3.6) D8(2.4,3.6) D9(3.2,3.6) E1(-3.2,2.8) E2(-2.4,2.8) E3(-1.6,2.8) E7(1.6,2.8) E8(2.4,2.8) E9(3.2,2.8) F1(-3.2,2) F2(-2.4,2) F3(-1.6,2) F7(1.6,2) F8(2.4,2) F9(3.2,2) G1(-3.2,1.2) G2(-2.4,1.2) G3(-1.6,1.2) G7(1.6,1.2) G8(2.4,1.2) G9(3.2,1.2) H1(-3.2,0.4) H2(-2.4,0.4) H3(-1.6,0.4) H7(1.6,0.4) H8(2.4,0.4) H9(3.2,0.4) J1(-3.2,-0.4) J2(-2.4,-0.4) J3(-1.6,-0.4) J7(1.6,-0.4) J8(2.4,-0.4) J9(3.2,-0.4) K1(-3.2,-1.2) K2(-2.4,-1.2) K3(-1.6,-1.2) K7(1.6,-1.2) K8(2.4,-1.2) K9(3.2,-1.2) L1(-3.2,-2) L2(-2.4,-2) L3(-1.6,-2) L7(1.6,-2) L8(2.4,-2) L9(3.2,-2) M1(-3.2,-2.8) M2(-2.4,-2.8) M3(-1.6,-2.8) M7(1.6,-2.8) M8(2.4,-2.8) M9(3.2,-2.8) N1(-3.2,-3.6) N2(-2.4,-3.6) N3(-1.6,-3.6) N7(1.6,-3.6) N8(2.4,-3.6) N9(3.2,-3.6) P1(-3.2,-4.4) P2(-2.4,-4.4) P3(-1.6,-4.4) P7(1.6,-4.4) P8(2.4,-4.4) P9(3.2,-4.4) R1(-3.2,-5.2) R2(-2.4,-5.2) R3(-1.6,-5.2) R7(1.6,-5.2) R8(2.4,-5.2) R9(3.2,-5.2) T1(-3.2,-6) T2(-2.4,-6) T3(-1.6,-6) T7(1.6,-6) T8(2.4,-6) T9(3.2,-6)
  silkscreen extent -3.93,-6.55 3.8,6.68, body extent -3.8,-6.55 3.8,6.55, height 1.21
ICC_LFBGA436_18X18_P080_H1P70_STM32MP257_CODE-B0D1 [mm] "MCD02000"
  round 0.3 smd paste+0.025 mask+0.05: A1(-8.4,8.4) A2(-7.6,8.4) A3(-6.8,8.4) A4(-6,8.4) A7(-3.6,8.4) A8(-2.8,8.4) A11(-0.4,8.4) A12(0.4,8.4) A15(2.8,8.4) A16(3.6,8.4) A19(6,8.4) A20(6.8,8.4) A21(7.6,8.4) A22(8.4,8.4) AA1(-8.4,-7.6) AA2(-7.6,-7.6) AA3(-6.8,-7.6) AA4(-6,-7.6) AA6(-4.4,-7.6) AA7(-3.6,-7.6) AA8(-2.8,-7.6) AA10(-1.2,-7.6) AA11(-0.4,-7.6) AA12(0.4,-7.6) AA14(2,-7.6) AA15(2.8,-7.6) AA16(3.6,-7.6) AA18(5.2,-7.6) AA19(6,-7.6) AA20(6.8,-7.6) AA21(7.6,-7.6) AA22(8.4,-7.6) AB1(-8.4,-8.4) AB2(-7.6,-8.4) AB3(-6.8,-8.4) AB4(-6,-8.4) AB7(-3.6,-8.4) AB8(-2.8,-8.4) AB11(-0.4,-8.4) AB12(0.4,-8.4) AB15(2.8,-8.4) AB16(3.6,-8.4) AB19(6,-8.4) AB20(6.8,-8.4) AB21(7.6,-8.4) AB22(8.4,-8.4) B1(-8.4,7.6) B2(-7.6,7.6) B3(-6.8,7.6) B4(-6,7.6) B5(-5.2,7.6) B7(-3.6,7.6) B8(-2.8,7.6) B9(-2,7.6) B11(-0.4,7.6) B12(0.4,7.6) B13(1.2,7.6) B15(2.8,7.6) B16(3.6,7.6) B17(4.4,7.6) B19(6,7.6) B20(6.8,7.6) B21(7.6,7.6) B22(8.4,7.6) C1(-8.4,6.8) C2(-7.6,6.8) C3(-6.8,6.8) C4(-6,6.8) C5(-5.2,6.8) C6(-4.4,6.8) C7(-3.6,6.8) C8(-2.8,6.8) C9(-2,6.8) C10(-1.2,6.8) C11(-0.4,6.8) C12(0.4,6.8) C13(1.2,6.8) C14(2,6.8) C15(2.8,6.8) C16(3.6,6.8) C17(4.4,6.8) C18(5.2,6.8) C19(6,6.8) C20(6.8,6.8) C21(7.6,6.8) C22(8.4,6.8) D1(-8.4,6) D2(-7.6,6) D3(-6.8,6) D4(-6,6) D5(-5.2,6) D6(-4.4,6) D7(-3.6,6) D8(-2.8,6) D9(-2,6) D10(-1.2,6) D11(-0.4,6) D12(0.4,6) D13(1.2,6) D14(2,6) D15(2.8,6) D16(3.6,6) D17(4.4,6) D18(5.2,6) D19(6,6) D20(6.8,6) D21(7.6,6) D22(8.4,6) E3(-6.8,5.2) E4(-6,5.2) E5(-5.2,5.2) E6(-4.4,5.2) E7(-3.6,5.2) E8(-2.8,5.2) E9(-2,5.2) E10(-1.2,5.2) E11(-0.4,5.2) E12(0.4,5.2) E13(1.2,5.2) E14(2,5.2) E15(2.8,5.2) E16(3.6,5.2) E17(4.4,5.2) E18(5.2,5.2) E19(6,5.2) E20(6.8,5.2) E21(7.6,5.2) F2(-7.6,4.4) F3(-6.8,4.4) F4(-6,4.4) F5(-5.2,4.4) F6(-4.4,4.4) F7(-3.6,4.4) F8(-2.8,4.4) F9(-2,4.4) F10(-1.2,4.4) F11(-0.4,4.4) F12(0.4,4.4) F13(1.2,4.4) F14(2,4.4) F15(2.8,4.4) F16(3.6,4.4) F17(4.4,4.4) F18(5.2,4.4) F19(6,4.4) F20(6.8,4.4) G1(-8.4,3.6) G2(-7.6,3.6) G3(-6.8,3.6) G4(-6,3.6) G5(-5.2,3.6) G6(-4.4,3.6) G7(-3.6,3.6) G8(-2.8,3.6) G9(-2,3.6) G10(-1.2,3.6) G11(-0.4,3.6) G12(0.4,3.6) G13(1.2,3.6) G14(2,3.6) G15(2.8,3.6) G16(3.6,3.6) G17(4.4,3.6) G18(5.2,3.6) G19(6,3.6) G20(6.8,3.6) G21(7.6,3.6) G22(8.4,3.6) H1(-8.4,2.8) H2(-7.6,2.8) H3(-6.8,2.8) H4(-6,2.8) H5(-5.2,2.8) H6(-4.4,2.8) H7(-3.6,2.8) H8(-2.8,2.8) H9(-2,2.8) H10(-1.2,2.8) H11(-0.4,2.8) H12(0.4,2.8) H13(1.2,2.8) H14(2,2.8) H15(2.8,2.8) H16(3.6,2.8) H17(4.4,2.8) H18(5.2,2.8) H19(6,2.8) H20(6.8,2.8) H21(7.6,2.8) H22(8.4,2.8) J3(-6.8,2) J4(-6,2) J5(-5.2,2) J6(-4.4,2) J7(-3.6,2) J8(-2.8,2) J9(-2,2) J10(-1.2,2) J11(-0.4,2) J12(0.4,2) J13(1.2,2) J14(2,2) J15(2.8,2) J16(3.6,2) J17(4.4,2) J18(5.2,2) J19(6,2) J20(6.8,2) J21(7.6,2) K2(-7.6,1.2) K3(-6.8,1.2) K4(-6,1.2) K5(-5.2,1.2) K6(-4.4,1.2) K7(-3.6,1.2) K8(-2.8,1.2) K9(-2,1.2) K10(-1.2,1.2) K11(-0.4,1.2) K12(0.4,1.2) K13(1.2,1.2) K14(2,1.2) K15(2.8,1.2) K16(3.6,1.2) K17(4.4,1.2) K18(5.2,1.2) K19(6,1.2) K20(6.8,1.2) L1(-8.4,0.4) L2(-7.6,0.4) L3(-6.8,0.4) L4(-6,0.4) L5(-5.2,0.4) L6(-4.4,0.4) L7(-3.6,0.4) L8(-2.8,0.4) L9(-2,0.4) L10(-1.2,0.4) L11(-0.4,0.4) L12(0.4,0.4) L13(1.2,0.4) L14(2,0.4) L15(2.8,0.4) L16(3.6,0.4) L17(4.4,0.4) L18(5.2,0.4) L19(6,0.4) L20(6.8,0.4) L21(7.6,0.4) L22(8.4,0.4) M1(-8.4,-0.4) M2(-7.6,-0.4) M3(-6.8,-0.4) M4(-6,-0.4) M5(-5.2,-0.4) M6(-4.4,-0.4) M7(-3.6,-0.4) M8(-2.8,-0.4) M9(-2,-0.4) M10(-1.2,-0.4) M11(-0.4,-0.4) M12(0.4,-0.4) M13(1.2,-0.4) M14(2,-0.4) M15(2.8,-0.4) M16(3.6,-0.4) M17(4.4,-0.4) M18(5.2,-0.4) M19(6,-0.4) M20(6.8,-0.4) M21(7.6,-0.4) M22(8.4,-0.4) N3(-6.8,-1.2) N4(-6,-1.2) N5(-5.2,-1.2) N6(-4.4,-1.2) N7(-3.6,-1.2) N8(-2.8,-1.2) N9(-2,-1.2) N10(-1.2,-1.2) N11(-0.4,-1.2) N12(0.4,-1.2) N13(1.2,-1.2) N14(2,-1.2) N15(2.8,-1.2) N16(3.6,-1.2) N17(4.4,-1.2) N18(5.2,-1.2) N19(6,-1.2) N20(6.8,-1.2) N21(7.6,-1.2) P2(-7.6,-2) P3(-6.8,-2) P4(-6,-2) P5(-5.2,-2) P6(-4.4,-2) P7(-3.6,-2) P8(-2.8,-2) P9(-2,-2) P10(-1.2,-2) P11(-0.4,-2) P12(0.4,-2) P13(1.2,-2) P14(2,-2) P15(2.8,-2) P16(3.6,-2) P17(4.4,-2) P18(5.2,-2) P19(6,-2) P20(6.8,-2) R1(-8.4,-2.8) R2(-7.6,-2.8) R3(-6.8,-2.8) R4(-6,-2.8) R5(-5.2,-2.8) R6(-4.4,-2.8) R7(-3.6,-2.8) R8(-2.8,-2.8) R9(-2,-2.8) R10(-1.2,-2.8) R11(-0.4,-2.8) R12(0.4,-2.8) R13(1.2,-2.8) R14(2,-2.8) R15(2.8,-2.8) R16(3.6,-2.8) R17(4.4,-2.8) R18(5.2,-2.8) R19(6,-2.8) R20(6.8,-2.8) R21(7.6,-2.8) R22(8.4,-2.8) T1(-8.4,-3.6) T2(-7.6,-3.6) T3(-6.8,-3.6) T4(-6,-3.6) T5(-5.2,-3.6) T6(-4.4,-3.6) T7(-3.6,-3.6) T8(-2.8,-3.6) T9(-2,-3.6) T10(-1.2,-3.6) T11(-0.4,-3.6) T12(0.4,-3.6) T13(1.2,-3.6) T14(2,-3.6) T15(2.8,-3.6) T16(3.6,-3.6) T17(4.4,-3.6) T18(5.2,-3.6) T19(6,-3.6) T20(6.8,-3.6) T21(7.6,-3.6) T22(8.4,-3.6) U3(-6.8,-4.4) U4(-6,-4.4) U5(-5.2,-4.4) U6(-4.4,-4.4) U7(-3.6,-4.4) U8(-2.8,-4.4) U9(-2,-4.4) U10(-1.2,-4.4) U11(-0.4,-4.4) U12(0.4,-4.4) U13(1.2,-4.4) U14(2,-4.4) U15(2.8,-4.4) U16(3.6,-4.4) U17(4.4,-4.4) U18(5.2,-4.4) U19(6,-4.4) U20(6.8,-4.4) U21(7.6,-4.4) V2(-7.6,-5.2) V3(-6.8,-5.2) V4(-6,-5.2) V5(-5.2,-5.2) V6(-4.4,-5.2) V7(-3.6,-5.2) V8(-2.8,-5.2) V9(-2,-5.2) V10(-1.2,-5.2) V11(-0.4,-5.2) V12(0.4,-5.2) V13(1.2,-5.2) V14(2,-5.2) V15(2.8,-5.2) V16(3.6,-5.2) V17(4.4,-5.2) V18(5.2,-5.2) V19(6,-5.2) V20(6.8,-5.2) W1(-8.4,-6) W2(-7.6,-6) W3(-6.8,-6) W4(-6,-6) W5(-5.2,-6) W6(-4.4,-6) W7(-3.6,-6) W8(-2.8,-6) W9(-2,-6) W10(-1.2,-6) W11(-0.4,-6) W12(0.4,-6) W13(1.2,-6) W14(2,-6) W15(2.8,-6) W16(3.6,-6) W17(4.4,-6) W18(5.2,-6) W19(6,-6) W20(6.8,-6) W21(7.6,-6) W22(8.4,-6) Y1(-8.4,-6.8) Y2(-7.6,-6.8) Y3(-6.8,-6.8) Y4(-6,-6.8) Y5(-5.2,-6.8) Y6(-4.4,-6.8) Y7(-3.6,-6.8) Y8(-2.8,-6.8) Y9(-2,-6.8) Y10(-1.2,-6.8) Y11(-0.4,-6.8) Y12(0.4,-6.8) Y13(1.2,-6.8) Y14(2,-6.8) Y15(2.8,-6.8) Y16(3.6,-6.8) Y17(4.4,-6.8) Y18(5.2,-6.8) Y19(6,-6.8) Y20(6.8,-6.8) Y21(7.6,-6.8) Y22(8.4,-6.8)
  silkscreen extent -9.25,-9.1 9.1,9.25, body extent -9.1,-9.1 9.1,9.1, height 1.7
ICC_P-WFBGA153_13X11P5_P050 [mm]
  round 0.23 smd mask+0.05: A1(-3.25,-3.25) A2(-3.25,-2.75) A3(-3.25,-2.25) A4(-3.25,-1.75) A5(-3.25,-1.25) A6(-3.25,-0.75) A7(-3.25,-0.25) A8(-3.25,0.25) A9(-3.25,0.75) A10(-3.25,1.25) A11(-3.25,1.75) A12(-3.25,2.25) A13(-3.25,2.75) A14(-3.25,3.25) B1(-2.75,-3.25) B2(-2.75,-2.75) B3(-2.75,-2.25) B4(-2.75,-1.75) B5(-2.75,-1.25) B6(-2.75,-0.75) B7(-2.75,-0.25) B8(-2.75,0.25) B9(-2.75,0.75) B10(-2.75,1.25) B11(-2.75,1.75) B12(-2.75,2.25) B13(-2.75,2.75) B14(-2.75,3.25) C1(-2.25,-3.25) C2(-2.25,-2.75) C3(-2.25,-2.25) C4(-2.25,-1.75) C5(-2.25,-1.25) C6(-2.25,-0.75) C7(-2.25,-0.25) C8(-2.25,0.25) C9(-2.25,0.75) C10(-2.25,1.25) C11(-2.25,1.75) C12(-2.25,2.25) C13(-2.25,2.75) C14(-2.25,3.25) D1(-1.75,-3.25) D2(-1.75,-2.75) D3(-1.75,-2.25) D4(-1.75,-1.75) D12(-1.75,2.25) D13(-1.75,2.75) D14(-1.75,3.25) E1(-1.25,-3.25) E2(-1.25,-2.75) E3(-1.25,-2.25) E5(-1.25,-1.25) E6(-1.25,-0.75) E7(-1.25,-0.25) E8(-1.25,0.25) E9(-1.25,0.75) E10(-1.25,1.25) E12(-1.25,2.25) E13(-1.25,2.75) E14(-1.25,3.25) F1(-0.75,-3.25) F2(-0.75,-2.75) F3(-0.75,-2.25) F5(-0.75,-1.25) F10(-0.75,1.25) F12(-0.75,2.25) F13(-0.75,2.75) F14(-0.75,3.25) G1(-0.25,-3.25) G2(-0.25,-2.75) G3(-0.25,-2.25) G5(-0.25,-1.25) G10(-0.25,1.25) G12(-0.25,2.25) G13(-0.25,2.75) G14(-0.25,3.25) H1(0.25,-3.25) H2(0.25,-2.75) H3(0.25,-2.25) H5(0.25,-1.25) H10(0.25,1.25) H12(0.25,2.25) H13(0.25,2.75) H14(0.25,3.25) J1(0.75,-3.25) J2(0.75,-2.75) J3(0.75,-2.25) J5(0.75,-1.25) J10(0.75,1.25) J12(0.75,2.25) J13(0.75,2.75) J14(0.75,3.25) K1(1.25,-3.25) K2(1.25,-2.75) K3(1.25,-2.25) K5(1.25,-1.25) K6(1.25,-0.75) K7(1.25,-0.25) K8(1.25,0.25) K9(1.25,0.75) K10(1.25,1.25) K12(1.25,2.25) K13(1.25,2.75) K14(1.25,3.25) L1(1.75,-3.25) L2(1.75,-2.75) L3(1.75,-2.25) L12(1.75,2.25) L13(1.75,2.75) L14(1.75,3.25) M1(2.25,-3.25) M2(2.25,-2.75) M3(2.25,-2.25) M4(2.25,-1.75) M5(2.25,-1.25) M6(2.25,-0.75) M7(2.25,-0.25) M8(2.25,0.25) M9(2.25,0.75) M10(2.25,1.25) M11(2.25,1.75) M12(2.25,2.25) M13(2.25,2.75) M14(2.25,3.25) N1(2.75,-3.25) N2(2.75,-2.75) N3(2.75,-2.25) N4(2.75,-1.75) N5(2.75,-1.25) N6(2.75,-0.75) N7(2.75,-0.25) N8(2.75,0.25) N9(2.75,0.75) N10(2.75,1.25) N11(2.75,1.75) N12(2.75,2.25) N13(2.75,2.75) N14(2.75,3.25) P1(3.25,-3.25) P2(3.25,-2.75) P3(3.25,-2.25) P4(3.25,-1.75) P5(3.25,-1.25) P6(3.25,-0.75) P7(3.25,-0.25) P8(3.25,0.25) P9(3.25,0.75) P10(3.25,1.25) P11(3.25,1.75) P12(3.25,2.25) P13(3.25,2.75) P14(3.25,3.25)
  silkscreen extent -6.78,-6.02 6.63,5.87, body extent -6.55,-5.8 6.55,5.8, height 1
ICC_QFN56-EPAD_6P5X6P5_P040 [mm] "MCD-03000"
  rect 0.55x0.21 smd mask+0.05: 1(-3.245,2.6) 14(-3.245,-2.6) 29(3.245,-2.6) 42(3.245,2.6)
  rect 0.7x0.21 smd mask+0.05: 2(-3.17,2.2) 3(-3.17,1.8) 4(-3.17,1.4) 5(-3.17,1) 6(-3.17,0.6) 7(-3.17,0.2) 8(-3.17,-0.2) 9(-3.17,-0.6) 10(-3.17,-1) 11(-3.17,-1.4) 12(-3.17,-1.8) 13(-3.17,-2.2) 30(3.17,-2.2) 31(3.17,-1.8) 32(3.17,-1.4) 33(3.17,-1) 34(3.17,-0.6) 35(3.17,-0.2) 36(3.17,0.2) 37(3.17,0.6) 38(3.17,1) 39(3.17,1.4) 40(3.17,1.8) 41(3.17,2.2)
  rect 0.21x0.55 smd mask+0.05: 15(-2.6,-3.245) 28(2.6,-3.245) 43(2.6,3.245) 56(-2.6,3.245)
  rect 0.21x0.7 smd mask+0.05: 16(-2.2,-3.17) 17(-1.8,-3.17) 18(-1.4,-3.17) 19(-1,-3.17) 20(-0.6,-3.17) 21(-0.2,-3.17) 22(0.2,-3.17) 23(0.6,-3.17) 24(1,-3.17) 25(1.4,-3.17) 26(1.8,-3.17) 27(2.2,-3.17) 44(2.2,3.17) 45(1.8,3.17) 46(1.4,3.17) 47(1,3.17) 48(0.6,3.17) 49(0.2,3.17) 50(-0.2,3.17) 51(-0.6,3.17) 52(-1,3.17) 53(-1.4,3.17) 54(-1.8,3.17) 55(-2.2,3.17)
  rect 4.7x4.7 smd mask+0.05: 57(0,0)
  Top Layer region: -2.495,2.97 -2.495,2.82 -2.555,2.82 -2.705,2.97
  Top Layer region: -2.495,-2.97 -2.495,-2.82 -2.555,-2.82 -2.705,-2.97
  Top Layer region: 2.495,2.97 2.495,2.82 2.555,2.82 2.705,2.97
  Top Layer region: -2.97,-2.495 -2.82,-2.495 -2.82,-2.555 -2.97,-2.705
  Top Layer region: 2.97,-2.495 2.82,-2.495 2.82,-2.555 2.97,-2.705
  Top Layer region: -2.97,2.495 -2.82,2.495 -2.82,2.555 -2.97,2.705
  Top Layer region: 2.495,-2.97 2.495,-2.82 2.555,-2.82 2.705,-2.97
  Top Layer region: 2.97,2.495 2.82,2.495 2.82,2.555 2.97,2.705
  silkscreen extent -3.44,3 -3.01,3.42, body extent -3.25,-3.25 3.25,3.25, height 0.91
IND_2016_MURATA_LQM2MPN2R2NG0 [mm]
  rect 0.8x1.8 smd mask+0.05: 1(-0.8,0) 2(0.8,0)
  silkscreen extent -0.28,-0.87 0.28,0.87, body extent -1.07,-0.87 1.08,0.87, height 1
IND_2520_TOKO_DFE252012P [mm]
  rect 0.8x2 smd mask+0.05: 1(-1,0) 2(1,0)
  silkscreen extent -1.35,-1.12 1.35,1.12, body extent -1.35,-1.1 1.35,1.1, height 2
LED_0603_OSRAM_LG-Q396-PS-35_GREEN_1A2K_H0P4 [mm]
  rect 0.8x0.8 smd mask+0.05: 1(-0.75,0) 2(0.75,0)
  silkscreen extent -0.85,-0.53 1.28,0.53, body extent -0.85,-0.45 0.85,0.45, height 0.6
LINK200 [mm]
  rect 0.2x0.35 smd paste-10 mask+0.05: 1(0,-0.225) 2(0,0.225)
R0201_H0P23 [mm] "MCD-00702"
  rect 0.4x0.5 smd mask+0.05: 1(-0.3,0) 2(0.3,0)
  body extent -0.32,-0.17 0.32,0.17, height 0.26
R0402 [mm]
  rect 0.51x0.7 smd mask+0.05: 1(-0.45,0) 2(0.45,0)
  body extent -0.52,-0.3 0.52,0.3, height 0.4
R0603 [mm]
  rect 0.64x1 smd mask+0.05: 1(-0.7,0) 2(0.7,0)
  silkscreen extent -1.05,-0.58 1.05,0.58, body extent -0.9,-0.5 0.9,0.5, height 0.56
SWI_WE_434121025816 [mm] "MCD-03492"
  rect 1.5x1.4 smd: 1(-3.25,0) 2(3.25,0)
  silkscreen extent -3,-1.95 3,1.95, body extent -3.65,-1.95 3.65,1.95, height 2.51
TP_SMD_1MM [mm]
  round 1 smd paste-10 mask+0.05: 1(0,0)
  silkscreen extent -0.7,-0.7 0.7,0.7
